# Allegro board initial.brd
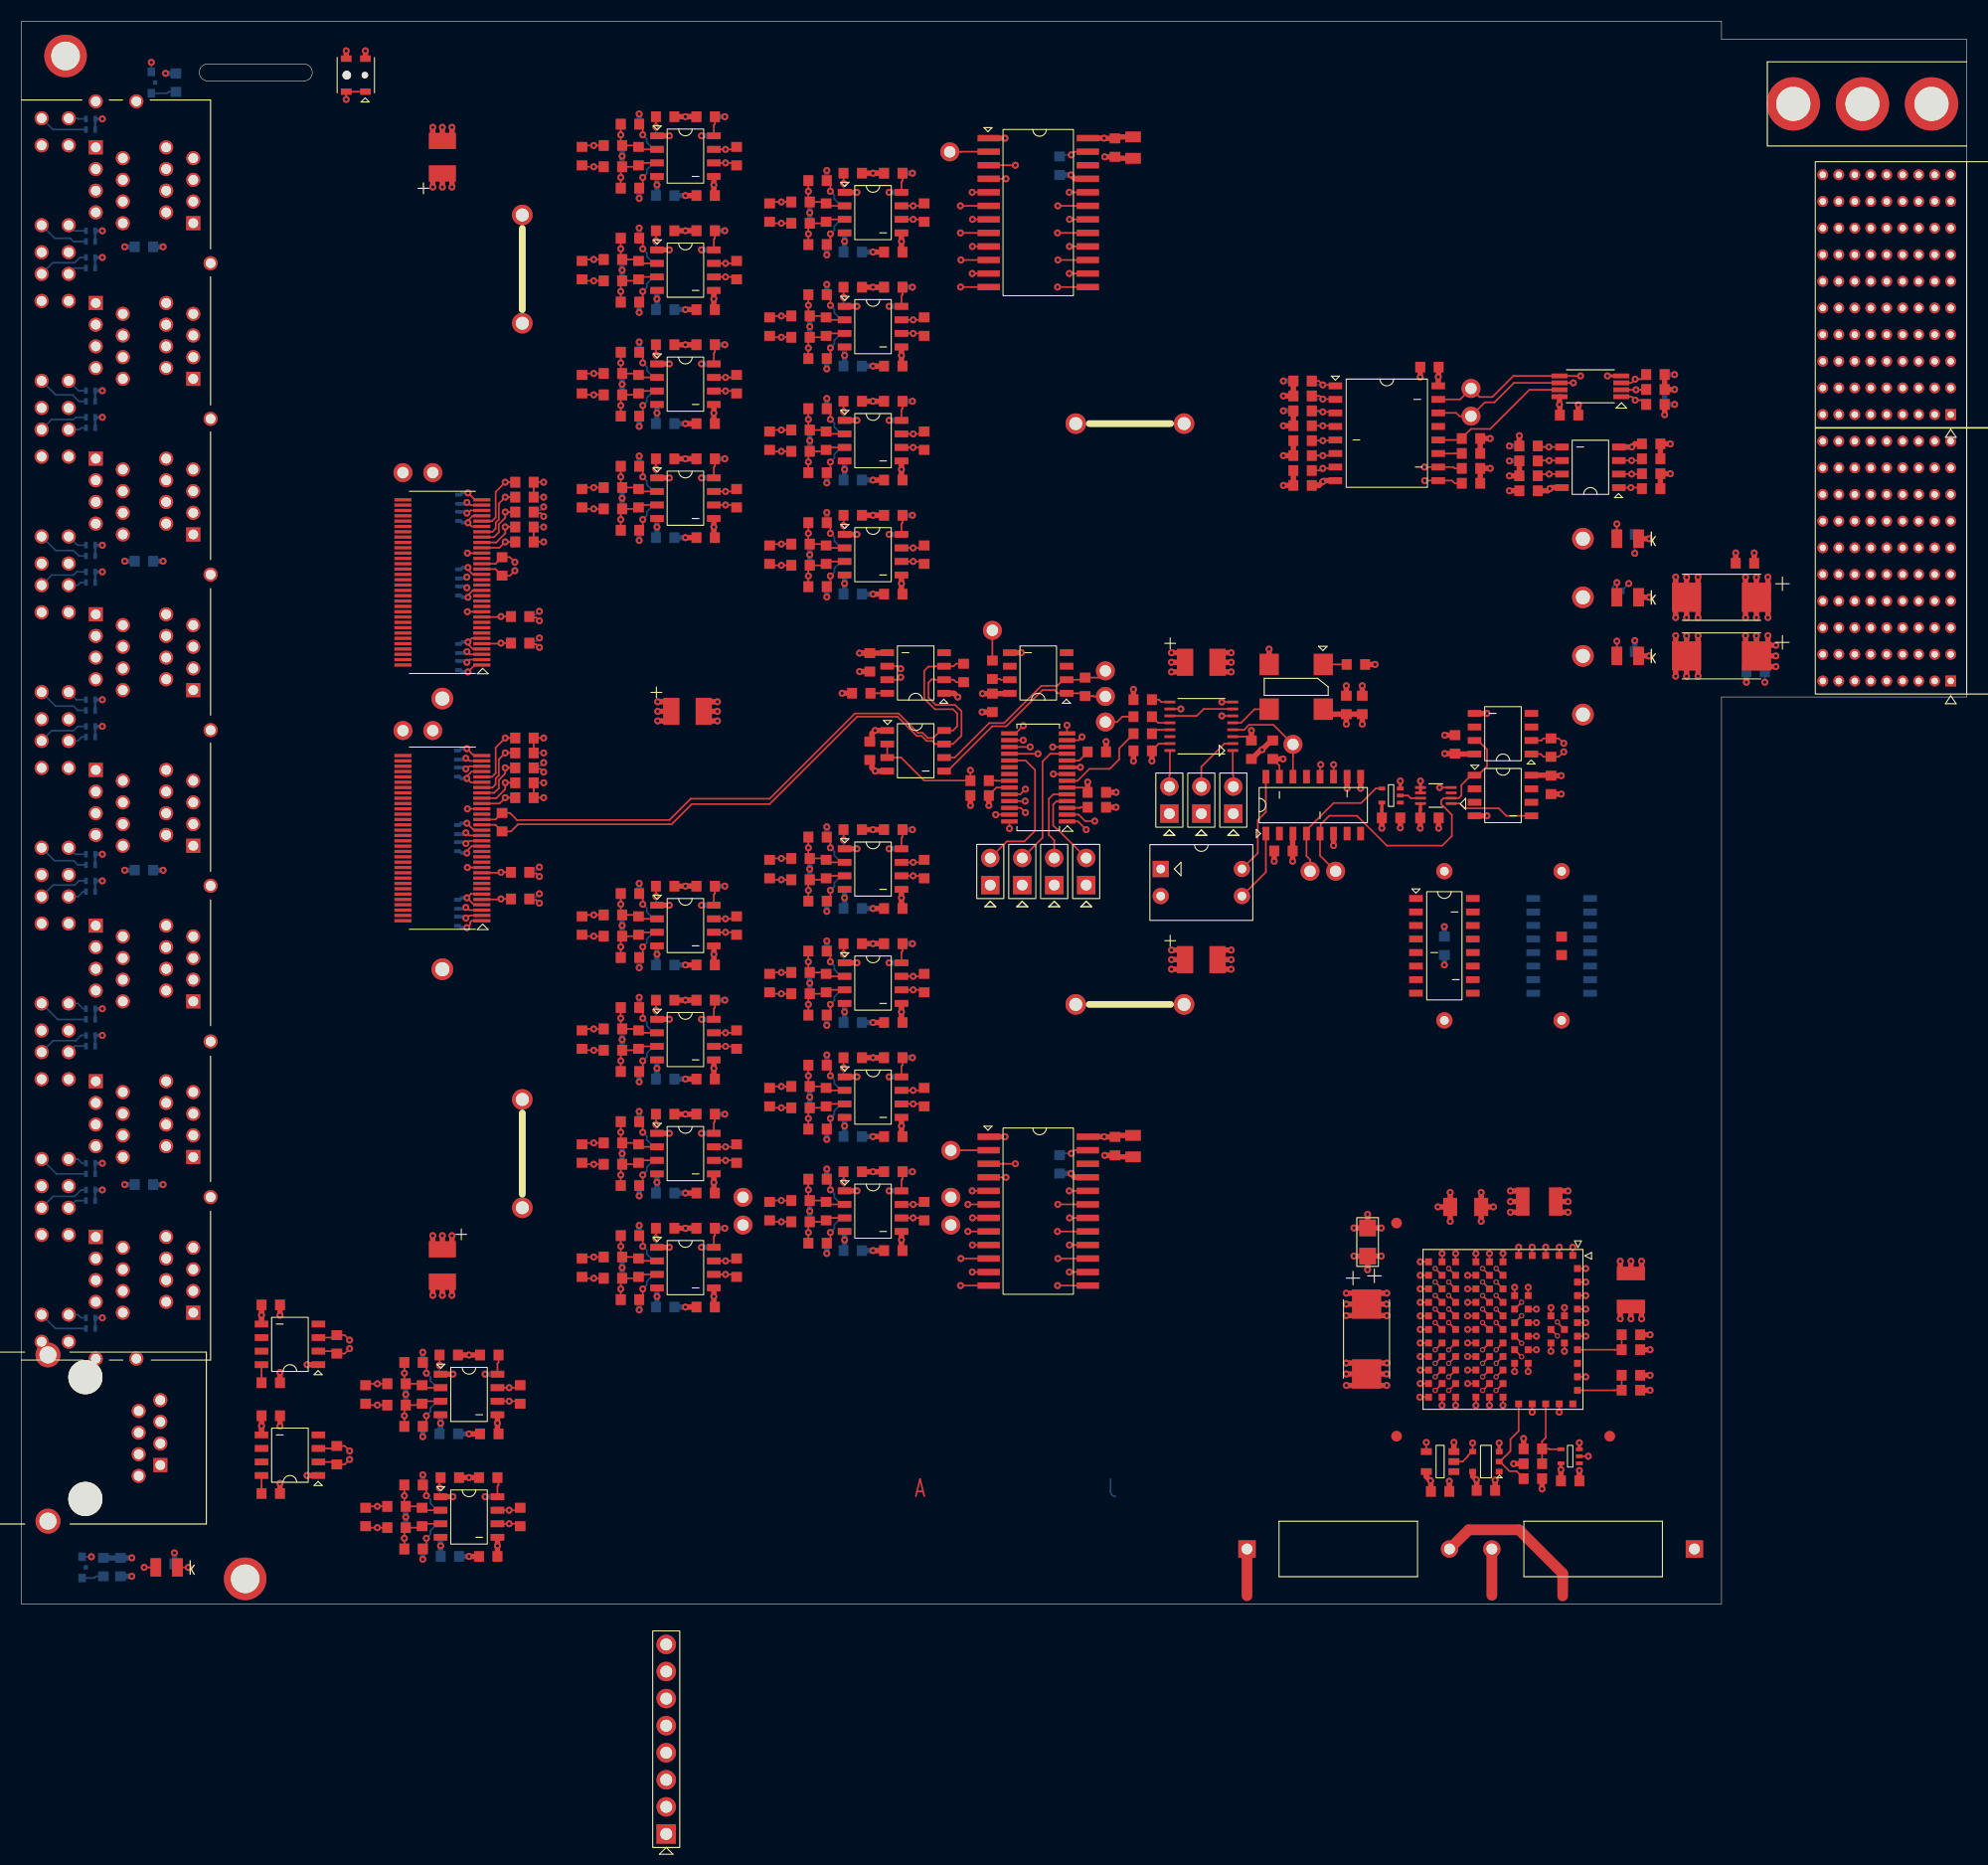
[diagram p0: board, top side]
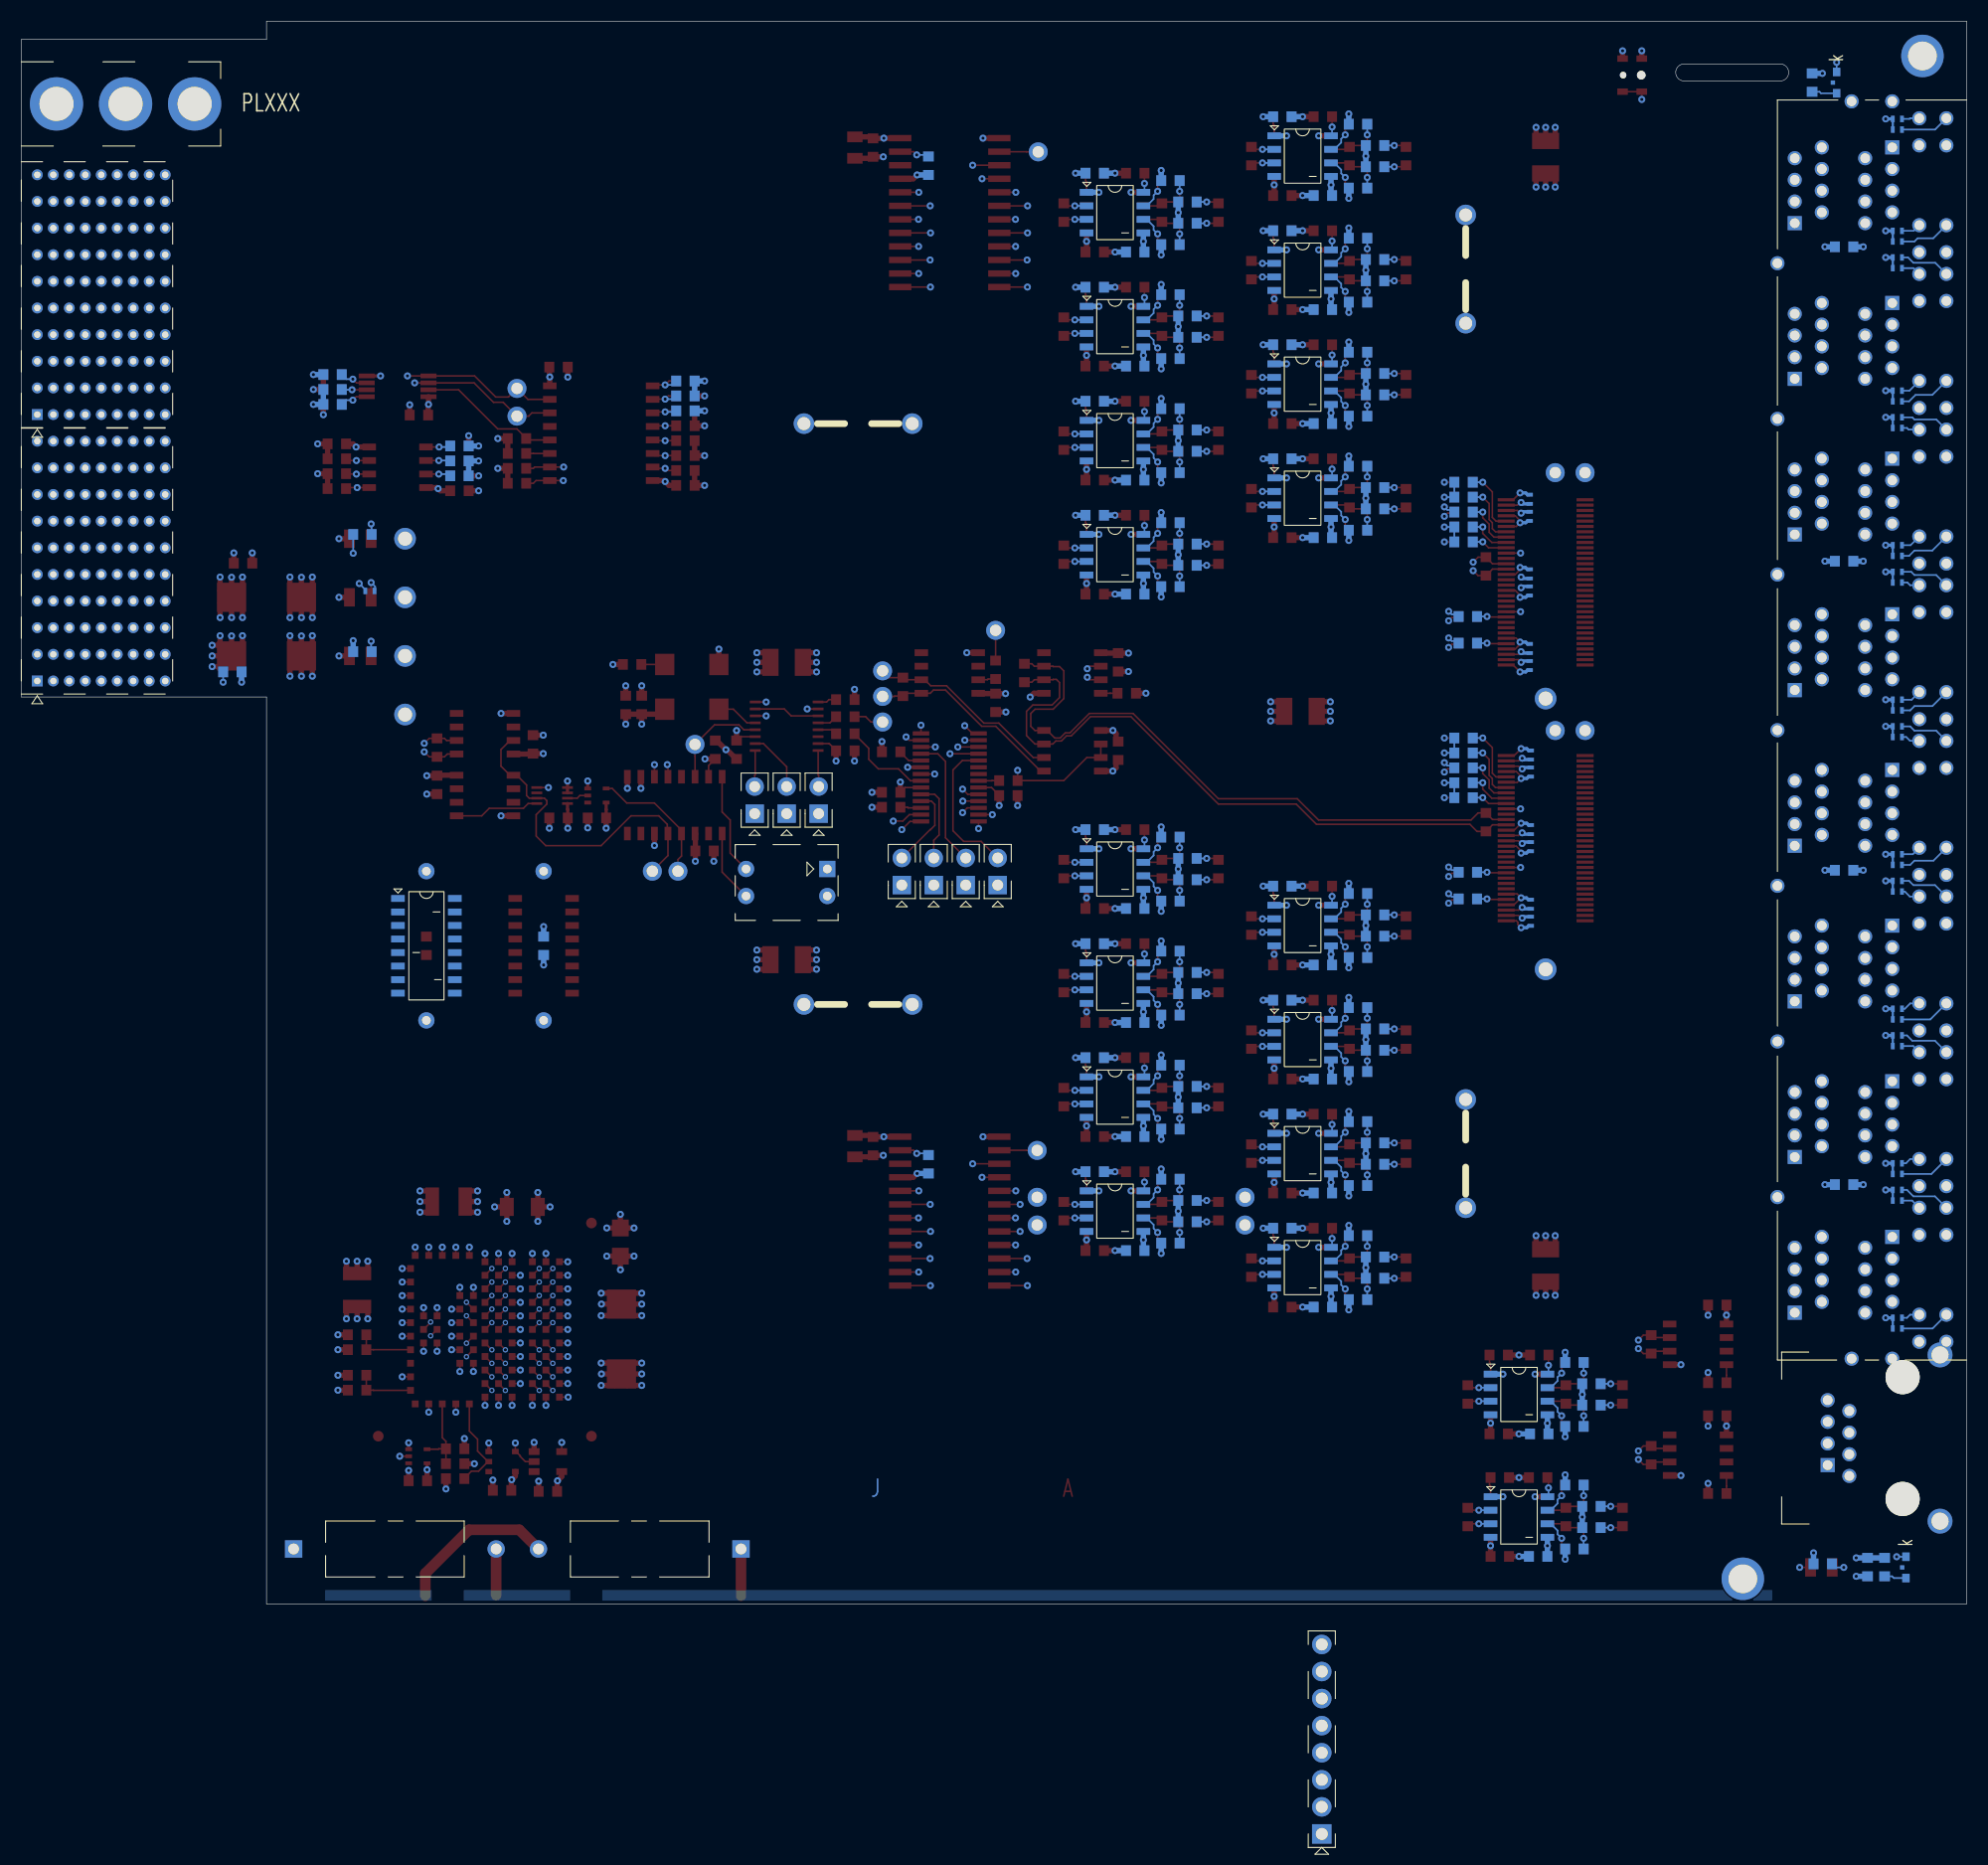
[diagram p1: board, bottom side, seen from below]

Outline 182.5 x 148.5 mm; copper layers: TOP, POWER, INNER TRACKS 1, POWER/GND1, INNER TRACKS 2, INNER TRACKS 3, POWER/GND2, INNER TRACKS 4, GND, BOTTOM. Coordinates in mm from the lower left corner of the outline.
Outline path: 0,148.5 0,0 159.5,0 159.5,85.1 182.5,85.1 182.5,146.8 159.5,146.8 159.5,148.5 0,148.5 ; 17.5,144.5 26.5,144.5 arc(27.3,143.7) 26.5,142.9 17.5,142.9 arc(16.7,143.7) 17.5,144.5

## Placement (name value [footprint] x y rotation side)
C1  -  [SMD0603M]  89.9 75.85 0 top
C2  -  [SMD0603M]  100.9 76.15 180 top
C3  -  [SMD0603M]  134.5 80.65 270 top
C4  -  [SMD0603M]  132.1 73.75 0 top
C5  -  [SMD0603M]  79.6 80.05 90 top
C6  -  [SMD0603M]  91.1 84.55 90 top
C7  -  [SMD0603M]  143.5 76.85 90 top
C8  -  [SMD0603M]  79.6 88.35 90 top
C9  -  [SMD0603M]  128.5 73.75 180 top
C10  -  [SMD0603M]  124.3 84.35 270 top
C11  -  [SMD0603M]  125.8 84.35 270 top
C12  -  [SMD0603M]  118.4 70.65 0 top
C13  -  [SMD0603M]  117.4 80.15 270 top
C14  -  [SMD0402]  40.9 65.65 270 bottom
C15  -  [SMD0402]  40.9 72.65 270 bottom
C16  -  [SMD0402]  40.9 79.65 270 bottom
C17  -  [SMD0402]  40.9 64.05 90 bottom
C18  -  [SMD0603]  55.5 134.85 180 bottom
C19  -  [SMD0603]  55.5 136.85 180 bottom
C20  -  [SMD0402]  40.9 71.05 90 bottom
C21  -  [SMD0402]  40.9 78.05 90 bottom
C22  -  [SMD0603M]  55.5 136.85 0 top
C23  -  [SMD0603M]  55.5 134.85 0 top
C24  -  [SMD0603M]  105.2 80.05 0 top
C25  -  [SMD0603M]  115.4 80.15 90 top
C26  -  [SMD0402]  41 103.65 270 bottom
C27  -  [SMD0402]  41 102.05 90 bottom
C28  -  [SMD0402]  41 96.65 270 bottom
C29  -  [SMD0402]  41 95.05 90 bottom
C30  -  [SMD0402]  41 89.65 270 bottom
C31  -  [SMD0402]  41 88.05 90 bottom
C32  -  [SMD0603]  35.2 7.15 180 bottom
C33  -  [SMD0603]  35.2 18.65 180 bottom
C34  -  [SMD0603]  35.2 9.15 180 bottom
C35  -  [SMD0603]  35.2 20.65 180 bottom
C36  -  [SMD0603M]  35.2 9.15 0 top
C37  -  [SMD0603M]  35.2 7.15 0 top
C38  -  [SMD0603M]  35.2 20.65 0 top
C39  -  [SMD0603M]  35.2 18.65 0 top
C40  -  [SMD0603M]  43.8 4.45 0 top
C41  -  [SMD0603M]  40.2 4.45 180 bottom
C42  -  [SMD0603M]  43.9 15.95 0 top
C43  -  [SMD0603M]  40.1 15.95 180 bottom
C44  -  [SMD0603M]  23.4 28.05 180 top
C45  -  [SMD0603M]  23.4 17.65 180 top
C46  -  [CASE_B]  62.5 83.75 180 top
C47  -  [CASE_B]  39.5 135.75 270 top
C48  -  [CASE_B]  39.5 31.75 90 top
C49  -  [CASE_B]  110.7 60.45 180 top
C50  -  [CASE_B]  110.7 88.35 180 top
C51  -  [SMD0603M]  64.2 118.15 180 bottom
C52  -  [SMD0603M]  64.2 139.55 180 bottom
C53  -  [SMD0603]  55.5 113.45 180 bottom
C54  -  [SMD0603M]  60.4 110.75 180 bottom
C55  -  [SMD0603M]  60.4 132.15 180 bottom
C56  -  [SMD0603]  55.5 115.45 180 bottom
C57  -  [SMD0603M]  64.2 110.75 0 top
C58  -  [SMD0603M]  64.2 132.15 0 top
C59  -  [SMD0603M]  55.5 115.45 0 top
C60  -  [SMD0603M]  55.5 113.45 0 top
C61  -  [SMD0603M]  64.2 107.45 180 bottom
C62  -  [SMD0603M]  64.2 128.85 180 bottom
C63  -  [SMD0603M]  60.4 100.05 180 bottom
C64  -  [SMD0603M]  60.4 121.45 180 bottom
C65  -  [SMD0603]  55.5 102.75 180 bottom
C66  -  [SMD0603]  55.5 124.15 180 bottom
C67  -  [SMD0603M]  64.2 100.05 0 top
C68  -  [SMD0603]  55.5 104.75 180 bottom
C69  -  [SMD0603]  55.5 126.15 180 bottom
C70  -  [SMD0603M]  64.2 121.45 0 top
C71  -  [SMD0603M]  55.5 104.75 0 top
C72  -  [SMD0603M]  55.5 102.75 0 top
C73  -  [SMD0603M]  55.5 126.15 0 top
C74  -  [SMD0603M]  55.5 124.15 0 top
C75  -  [SMD0603M]  133.1 10.55 180 top
C76  -  [SMD0603M]  137.4 10.65 180 top
C77  -  [SMD0603M]  132.1 116.05 0 top
C78  -  [CASE_D]  159.5 88.95 0 top
C79  -  [SMD1210M]  142.4 37.75 0 top
C80  -  [SMD1210M]  151 29.45 90 top
C81  -  [SMD0603]  151 25.25 180 top
C82  -  [SMD0603M]  151 21.45 0 top
C83  -  [SMD1206]  135.5 37.25 180 top
C84  -  [CASE_E]  126.2 24.85 90 top
C85  -  [SMD0603M]  145.2 111.55 180 top
C86  -  [SMD0603M]  9.3 3.45 90 bottom
C87  -  [SMD0603M]  120.2 104.95 180 top
C88  -  [SMD0603M]  152.9 108.85 0 top
C89  -  [SMD0603M]  161.7 97.65 0 top
C90  -  [SMD0603M]  141.4 104.45 0 top
C91  -  [CASE_E]  159.5 94.45 0 top
C92  -  [SMD0603M]  64.2 45.95 180 bottom
C93  -  [SMD0603M]  64.2 67.35 180 bottom
C94  -  [SMD0603]  55.5 41.25 180 bottom
C95  -  [SMD0603M]  60.4 38.55 180 bottom
C96  -  [SMD0603M]  60.4 59.95 180 bottom
C97  -  [SMD0603]  55.5 62.65 180 bottom
C98  -  [SMD0603]  55.5 43.25 180 bottom
C99  -  [SMD0603M]  64.2 38.55 0 top
C100  -  [SMD0603]  55.5 64.65 180 bottom
C101  -  [SMD0603M]  64.2 59.95 0 top
C102  -  [SMD0603M]  55.5 43.25 0 top
C103  -  [SMD0603M]  55.5 41.25 0 top
C104  -  [SMD0603M]  55.5 64.65 0 top
C105  -  [SMD0603M]  55.5 62.65 0 top
C106  -  [SMD0603M]  64.2 35.25 180 bottom
C107  -  [SMD0603M]  64.2 56.65 180 bottom
C108  -  [SMD0603M]  60.4 27.85 180 bottom
C109  -  [SMD0603M]  60.4 49.25 180 bottom
C110  -  [SMD0603]  55.5 30.55 180 bottom
C111  -  [SMD0603]  55.5 51.95 180 bottom
C112  -  [SMD0603]  55.5 32.55 180 bottom
C113  -  [SMD0603]  55.5 53.95 180 bottom
C114  -  [SMD0603M]  64.2 27.85 0 top
C115  -  [SMD0603M]  64.2 49.25 0 top
C116  -  [SMD0603M]  55.5 32.55 0 top
C117  -  [SMD0603M]  55.5 30.55 0 top
C118  -  [SMD0603M]  55.5 53.95 0 top
C119  -  [SMD0603M]  55.5 51.95 0 top
C120  -  [SMD0603M]  81.8 72.65 180 bottom
C121  -  [SMD0603M]  81.8 43.85 0 top
C122  -  [SMD0603]  73.1 46.55 180 bottom
C123  -  [SMD0603M]  78 65.25 180 bottom
C124  -  [SMD0603M]  78 43.85 180 bottom
C125  -  [SMD0603]  73.1 67.95 180 bottom
C126  -  [SMD0603]  73.1 48.55 180 bottom
C127  -  [SMD0603]  73.1 69.95 180 bottom
C128  -  [SMD0603M]  81.8 65.25 0 top
C129  -  [SMD0603M]  81.8 51.25 180 bottom
C130  -  [SMD0603M]  73.1 48.55 0 top
C131  -  [SMD0603M]  73.1 46.55 0 top
C132  -  [SMD0603M]  73.1 69.95 0 top
C133  -  [SMD0603M]  73.1 67.95 0 top
C134  -  [SMD0603M]  81.8 54.55 0 top
C135  -  [SMD0603M]  81.8 40.55 180 bottom
C136  -  [SMD0603M]  78 54.55 180 bottom
C137  -  [SMD0603]  73.1 35.85 180 bottom
C138  -  [SMD0603M]  81.8 33.15 0 top
C139  -  [SMD0603]  73.1 57.25 180 bottom
C140  -  [SMD0603]  73.1 37.85 180 bottom
C141  -  [SMD0603]  73.1 59.25 180 bottom
C142  -  [SMD0603M]  81.8 61.95 180 bottom
C143  -  [SMD0603M]  78 33.15 180 bottom
C144  -  [SMD0603M]  73.1 37.85 0 top
C145  -  [SMD0603M]  73.1 35.85 0 top
C146  -  [SMD0603M]  73.1 59.25 0 top
C147  -  [SMD0603M]  73.1 57.25 0 top
C148  -  [SMD0603M]  81.8 134.25 180 bottom
C149  -  [SMD0603M]  81.8 112.85 180 bottom
C150  -  [SMD0603]  73.1 108.15 180 bottom
C151  -  [SMD0603M]  78 126.85 180 bottom
C152  -  [SMD0603M]  78 105.45 180 bottom
C153  -  [SMD0603]  73.1 129.55 180 bottom
C154  -  [SMD0603]  73.1 110.15 180 bottom
C155  -  [SMD0603]  73.1 131.55 180 bottom
C156  -  [SMD0603M]  81.8 126.85 0 top
C157  -  [SMD0603M]  81.8 105.45 0 top
C158  -  [SMD0603M]  73.1 110.15 0 top
C159  -  [SMD0603M]  73.1 108.15 0 top
C160  -  [SMD0603M]  73.1 131.55 0 top
C161  -  [SMD0603M]  73.1 129.55 0 top
C162  -  [SMD0603M]  81.8 123.55 180 bottom
C163  -  [SMD0603M]  81.8 102.15 180 bottom
C164  -  [SMD0603M]  78 116.15 180 bottom
C165  -  [SMD0603]  73.1 97.45 180 bottom
C166  -  [SMD0603M]  78 94.75 180 bottom
C167  -  [SMD0603]  73.1 118.85 180 bottom
C168  -  [SMD0603]  73.1 99.45 180 bottom
C169  -  [SMD0603]  73.1 120.85 180 bottom
C170  -  [SMD0603M]  81.8 116.15 0 top
C171  -  [SMD0603M]  81.8 94.75 0 top
C172  -  [SMD0603M]  73.1 99.45 0 top
C173  -  [SMD0603M]  73.1 97.45 0 top
C174  -  [SMD0603M]  73.1 120.85 0 top
C175  -  [SMD0603M]  73.1 118.85 0 top
C176  -  [SMD0603M]  11.5 127.34 180 bottom
C177  -  [SMD0603M]  11.5 97.84 180 bottom
C178  -  [SMD0603M]  11.5 68.84 180 bottom
C179  -  [SMD0603M]  11.5 39.34 180 bottom
C180  -  [SMD0603M]  145.3 11.55 180 top
C181  -  [SMD0603M]  102.6 136.65 90 top
C182  -  [SMD0805M]  104.3 136.65 90 top
C183  -  [SMD0603M]  102.6 42.95 90 top
C184  -  [SMD0805M]  104.3 42.95 90 top
C185  -  [CASE_A]  126.3 33.95 270 top
C186  -  [SMD0603M]  133.5 61.75 90 bottom
C187  -  [SMD0603M]  144.5 61.75 90 top
DS1  -  [SMD0805_LED]  13.63 3.42 0 top
DS2  -  [SMD0805_LED]  150.7 88.95 0 top
DS3  -  [SMD0805_LED]  150.7 94.45 0 top
DS4  -  [SMD0805_LED]  150.7 99.95 0 top
DS5  -  [LED_C120]  12.2 142.75 90 bottom
DS6  -  [LED_C120]  5.7 3.42 90 bottom
LK5  -  [JUMPER2X1_0-4]  47 130.33 270 top
LK6  -  [JUMPER2X1_0-4]  47 47.33 270 top
LK7  -  [JUMPER2X1_0-4]  98.92 110.75 0 top
LK8  -  [JUMPER2X1_0-4]  98.92 56.25 0 top
LK9  -  [1-HOLE_0-8P]  133.5 54.75 0 top
LK10  -  [1-HOLE_0-8P]  144.5 54.75 0 top
LK11  -  [1-HOLE_0-8P]  133.5 68.75 0 top
LK12  -  [1-HOLE_0-8P]  144.5 68.75 0 top
NOREF  -  []  324.06 192.95 0 top
NOREF#2  -  []  338.25 207.28 270 top
NOREF#3  -  []  303.96 193.41 0 top
NOREF#4  -  []  301.8 201.69 0 top
NOREF#5  -  []  305.51 178.63 0 top
NOREF#6  -  [unnamed#3]  4.15 145.25 0 top
NOREF#7  -  []  126.54 -124.33 0 top
NOREF#8  -  []  14.14 -124.33 0 top
NOREF#9  -  [unnamed#3]  21 2.35 0 top
NOREF#10  -  []  314.1 193.26 0 top
NOREF#11  -  []  317.37 209.01 180 top
NOREF#12  -  []  -79.18 -149.14 0 top
NOREF#13  -  []  302.03 169.94 0 top
NOREF#14  -  []  330.15 201.21 90 top
PL1  -  [HEADER2X1_STR]  93.9 67.45 90 top
PL2  -  [HEADER2X1_STR]  99.9 67.45 90 top
PL3  -  [HEADER2X1_STR]  96.9 67.45 90 top
PL4  -  [HEADER2X1_STR]  90.9 67.45 90 top
PL5  -  [HEADER2X1_STR]  107.7 74.15 90 top
PL6  -  [HEADER2X1_STR]  113.7 74.15 90 top
PL7  -  [HEADER2X1_STR]  110.7 74.15 90 top
PL8  -  [UNIVERSAL_GUIDE_PIN]  179.2 140.75 180 top
PL9  -  [PL_DIFF_30PAIRS_RT-ANG]  181 86.6 90 top
PL10  -  [PL_DIFF_30PAIRS_RT-ANG]  181 111.6 90 top
PL11  -  [HEADER1X8_STR]  60.5 -31.75 90 top
R1  -  [SMD0603]  100.9 74.75 180 top
R2  -  [SMD0603]  100.9 79.95 180 top
R3  -  [SMD0603]  89.9 77.25 180 top
R4  -  [SMD0603]  99.8 86.05 90 top
R5  -  [SMD0603]  91.1 87.65 90 top
R6  -  [SMD0603]  47.2 81.25 0 top
R7  -  [SMD0603]  47.2 81.25 180 bottom
R8  -  [SMD0603]  47.2 75.65 0 top
R9  -  [SMD0603]  47.2 75.65 180 bottom
R10  -  [SMD0603]  46.8 68.65 0 top
R11  -  [SMD0603]  46.8 68.65 180 bottom
R12  -  [SMD0603]  46.8 66.15 0 top
R13  -  [SMD0603]  46.8 66.15 180 bottom
R14  -  [SMD0603]  47.2 79.85 0 top
R15  -  [SMD0603]  47.2 79.85 180 bottom
R16  -  [SMD0603]  47.2 78.45 0 top
R17  -  [SMD0603]  47.2 78.45 180 bottom
R18  -  [SMD0603]  47.2 77.05 0 top
R19  -  [SMD0603]  47.2 77.05 180 bottom
R20  -  [SMD0603]  52.6 135.85 90 top
R21  -  [SMD0603]  88.4 87.35 270 top
R22  -  [SMD0603]  125.2 88.15 0 top
R23  -  [SMD0603]  78.8 85.45 180 top
R24  -  [SMD0603]  57.1 138.85 0 top
R25  -  [SMD0603]  57.9 135.85 90 top
R26  -  [SMD0603]  57.1 132.85 180 top
R27  -  [SMD0603]  57.1 138.85 0 bottom
R28  -  [SMD0603]  57.1 132.85 180 bottom
R29  -  [SMD0603]  105.2 84.85 180 top
R30  -  [SMD0603]  105.2 81.65 180 top
R31  -  [SMD0603]  105.2 83.25 180 top
R32  -  [SMD0402]  6.5 138.34 180 bottom
R33  -  [SMD0402]  6.5 127.84 180 bottom
R34  -  [SMD0402]  6.5 126.34 180 bottom
R35  -  [SMD0603]  64.2 139.55 180 top
R36  -  [SMD0402]  6.5 112.84 180 bottom
R37  -  [SMD0603]  67.1 135.85 90 top
R38  -  [SMD0402]  6.5 111.34 180 bottom
R39  -  [SMD0603]  60.4 139.55 0 top
R40  -  [SMD0402]  6.5 98.34 180 bottom
R41  -  [SMD0402]  6.5 96.84 180 bottom
R42  -  [SMD0402]  6.5 83.84 180 bottom
R43  -  [SMD0402]  6.5 82.34 180 bottom
R44  -  [SMD0402]  6.5 69.34 180 bottom
R45  -  [SMD0402]  6.5 67.84 180 bottom
R46  -  [SMD0402]  6.5 54.84 180 bottom
R47  -  [SMD0402]  6.5 53.34 180 bottom
R48  -  [SMD0402]  6.5 40.34 180 bottom
R49  -  [SMD0402]  6.5 38.84 180 bottom
R50  -  [SMD0402]  6.5 25.84 180 bottom
R51  -  [SMD0402]  6.5 139.34 0 bottom
R52  -  [SMD0402]  6.5 128.84 0 bottom
R53  -  [SMD0402]  6.5 125.34 0 bottom
R54  -  [SMD0402]  6.5 113.84 0 bottom
R55  -  [SMD0402]  6.5 110.34 0 bottom
R56  -  [SMD0402]  6.5 99.34 0 bottom
R57  -  [SMD0402]  6.5 95.84 0 bottom
R58  -  [SMD0402]  6.5 84.84 0 bottom
R59  -  [SMD0402]  6.5 81.34 0 bottom
R60  -  [SMD0402]  6.5 70.34 0 bottom
R61  -  [SMD0402]  6.5 66.84 0 bottom
R62  -  [SMD0402]  6.5 55.84 0 bottom
R63  -  [SMD0402]  6.5 52.34 0 bottom
R64  -  [SMD0402]  6.5 41.34 0 bottom
R65  -  [SMD0402]  6.5 37.84 0 bottom
R66  -  [SMD0402]  6.5 26.84 0 bottom
R67  -  [SMD0603]  45.1 97.35 270 top
R68  -  [SMD0603]  46.8 92.65 0 top
R69  -  [SMD0603]  46.8 92.65 180 bottom
R70  -  [SMD0603]  46.8 90.15 0 top
R71  -  [SMD0603]  46.8 90.15 180 bottom
R72  -  [SMD0603]  47.2 103.85 0 top
R73  -  [SMD0603]  47.2 103.85 180 bottom
R74  -  [SMD0603]  47.2 102.45 0 top
R75  -  [SMD0603]  47.2 102.45 180 bottom
R76  -  [SMD0603]  47.2 101.05 0 top
R77  -  [SMD0603]  47.2 101.05 180 bottom
R78  -  [SMD0603]  47.2 105.25 0 top
R79  -  [SMD0603]  47.2 105.25 180 bottom
R80  -  [SMD0603]  47.2 99.65 0 top
R81  -  [SMD0603]  47.2 99.65 180 bottom
R82  -  [SMD0603]  32.3 8.15 90 top
R83  -  [SMD0603]  32.3 19.65 90 top
R84  -  [SMD0603]  36.8 11.15 0 top
R85  -  [SMD0603]  37.6 8.15 90 top
R86  -  [SMD0603]  36.8 5.15 180 top
R87  -  [SMD0603]  36.8 22.65 0 top
R88  -  [SMD0603]  37.6 19.65 90 top
R89  -  [SMD0603]  36.8 16.65 180 top
R90  -  [SMD0603]  36.8 5.15 180 bottom
R91  -  [SMD0603]  36.8 16.65 180 bottom
R92  -  [SMD0603]  36.8 11.15 0 bottom
R93  -  [SMD0603]  36.8 22.65 0 bottom
R94  -  [SMD0603]  43.8 11.85 180 top
R95  -  [SMD0603]  43.9 23.35 180 top
R96  -  [SMD0603]  46.8 8.15 90 top
R97  -  [SMD0603]  46.8 19.65 90 top
R98  -  [SMD0603]  40.2 11.85 0 top
R99  -  [SMD0603]  40.1 23.35 0 top
R100  -  [SMD0603]  29.6 24.35 270 top
R101  -  [SMD0603]  29.6 13.95 270 top
R102  -  [SMD0603]  23.4 20.75 0 top
R103  -  [SMD0603]  23.4 10.35 0 top
R104  -  [SMD0603]  52.6 114.45 90 top
R105  -  [SMD0603]  57.1 117.45 0 top
R106  -  [SMD0603]  57.9 114.45 90 top
R107  -  [SMD0603]  57.1 111.45 180 top
R108  -  [SMD0603]  57.1 117.45 0 bottom
R109  -  [SMD0603]  57.1 111.45 180 bottom
R110  -  [SMD0603]  64.2 118.15 180 top
R111  -  [SMD0603]  67.1 114.45 90 top
R112  -  [SMD0603]  60.4 118.15 0 top
R113  -  [SMD0603]  52.6 103.75 90 top
R114  -  [SMD0603]  52.6 125.15 90 top
R115  -  [SMD0603]  57.1 106.75 0 top
R116  -  [SMD0603]  57.9 103.75 90 top
R117  -  [SMD0603]  57.1 100.75 180 top
R118  -  [SMD0603]  57.1 128.15 0 top
R119  -  [SMD0603]  57.9 125.15 90 top
R120  -  [SMD0603]  57.1 122.15 180 top
R121  -  [SMD0603]  57.1 106.75 0 bottom
R122  -  [SMD0603]  57.1 100.75 180 bottom
R123  -  [SMD0603]  57.1 128.15 0 bottom
R124  -  [SMD0603]  57.1 122.15 180 bottom
R125  -  [SMD0603]  64.2 107.45 180 top
R126  -  [SMD0603]  64.2 128.85 180 top
R127  -  [SMD0603]  67.1 103.75 90 top
R128  -  [SMD0603]  67.1 125.15 90 top
R129  -  [SMD0603]  60.4 107.45 0 top
R130  -  [SMD0603]  60.4 128.85 0 top
R131  -  [SMD0603]  150.5 89.35 180 bottom
R132  -  [SMD0402]  149.8 95.05 180 bottom
R133  -  [SMD0603]  141.8 11.75 0 top
R134  -  [SMD0603]  150.5 100.35 180 bottom
R135  -  [SMD0603]  141.8 14.55 180 top
R136  -  [SMD0603]  141.8 13.15 0 top
R137  -  [SMD0603]  151 23.85 180 top
R138  -  [SMD0603]  120.2 114.75 180 top
R139  -  [SMD0603]  120.2 110.55 180 top
R140  -  [SMD0603]  120.2 109.15 180 top
R141  -  [SMD0603]  120.2 107.75 180 top
R142  -  [SMD0603]  120.2 106.35 180 top
R143  -  [SMD0603]  136 105.15 0 top
R144  -  [SMD0603]  151 20.05 180 top
R145  -  [SMD0603]  136 106.55 0 top
R146  -  [SMD0603]  136 107.95 0 top
R147  -  [SMD0603]  136 109.35 0 top
R148  -  [SMD0603]  153.3 115.35 0 top
R149  -  [SMD0603]  152.9 104.65 0 top
R150  -  [SMD0603]  152.9 106.05 0 top
R151  -  [SMD0603]  14.5 142.75 270 bottom
R152  -  [SMD0603]  7.7 3.45 270 bottom
R153  -  [SMD0603]  13.5 3.75 180 bottom
R154  -  [SMD0603]  141.4 108.65 180 top
R155  -  [SMD0603]  141.4 108.65 0 bottom
R156  -  [SMD0603]  141.4 107.25 180 top
R157  -  [SMD0603]  141.4 107.25 0 bottom
R158  -  [SMD0603]  141.4 105.85 180 top
R159  -  [SMD0603]  141.4 105.85 0 bottom
R160  -  [SMD0603]  152.9 107.45 0 top
R161  -  [SMD0603]  52.6 42.25 90 top
R162  -  [SMD0603]  52.6 63.65 90 top
R163  -  [SMD0603]  57.1 45.25 0 top
R164  -  [SMD0603]  57.9 42.25 90 top
R165  -  [SMD0603]  57.1 39.25 180 top
R166  -  [SMD0603]  57.1 45.25 0 bottom
R167  -  [SMD0603]  57.1 39.25 180 bottom
R168  -  [SMD0603]  57.1 66.65 0 top
R169  -  [SMD0603]  57.9 63.65 90 top
R170  -  [SMD0603]  57.1 60.65 180 top
R171  -  [SMD0603]  57.1 66.65 0 bottom
R172  -  [SMD0603]  57.1 60.65 180 bottom
R173  -  [SMD0603]  64.2 45.95 180 top
R174  -  [SMD0603]  64.2 67.35 180 top
R175  -  [SMD0603]  67.1 42.25 90 top
R176  -  [SMD0603]  67.1 63.65 90 top
R177  -  [SMD0603]  60.4 45.95 0 top
R178  -  [SMD0603]  60.4 67.35 0 top
R179  -  [SMD0603]  52.6 31.55 90 top
R180  -  [SMD0603]  52.6 52.95 90 top
R181  -  [SMD0603]  57.1 34.55 0 top
R182  -  [SMD0603]  57.9 31.55 90 top
R183  -  [SMD0603]  57.1 28.55 180 top
R184  -  [SMD0603]  57.1 55.95 0 top
R185  -  [SMD0603]  57.9 52.95 90 top
R186  -  [SMD0603]  57.1 49.95 180 top
R187  -  [SMD0603]  57.1 34.55 0 bottom
R188  -  [SMD0603]  57.1 28.55 180 bottom
R189  -  [SMD0603]  57.1 55.95 0 bottom
R190  -  [SMD0603]  57.1 49.95 180 bottom
R191  -  [SMD0603]  64.2 35.25 180 top
R192  -  [SMD0603]  64.2 56.65 180 top
R193  -  [SMD0603]  67.1 31.55 90 top
R194  -  [SMD0603]  67.1 52.95 90 top
R195  -  [SMD0603]  60.4 35.25 0 top
R196  -  [SMD0603]  60.4 56.65 0 top
R197  -  [SMD0603]  70.2 47.55 90 top
R198  -  [SMD0603]  70.2 68.95 90 top
R199  -  [SMD0603]  74.7 50.55 0 top
R200  -  [SMD0603]  75.5 47.55 90 top
R201  -  [SMD0603]  74.7 44.55 180 top
R202  -  [SMD0603]  74.7 50.55 0 bottom
R203  -  [SMD0603]  74.7 44.55 180 bottom
R204  -  [SMD0603]  74.7 71.95 0 top
R205  -  [SMD0603]  75.5 68.95 90 top
R206  -  [SMD0603]  74.7 65.95 180 top
R207  -  [SMD0603]  74.7 71.95 0 bottom
R208  -  [SMD0603]  74.7 65.95 180 bottom
R209  -  [SMD0603]  81.8 51.25 180 top
R210  -  [SMD0603]  81.8 72.65 180 top
R211  -  [SMD0603]  84.7 47.55 90 top
R212  -  [SMD0603]  84.7 68.95 90 top
R213  -  [SMD0603]  78 51.25 0 top
R214  -  [SMD0603]  78 72.65 0 top
R215  -  [SMD0603]  70.2 36.85 90 top
R216  -  [SMD0603]  70.2 58.25 90 top
R217  -  [SMD0603]  74.7 39.85 0 top
R218  -  [SMD0603]  75.5 36.85 90 top
R219  -  [SMD0603]  74.7 33.85 180 top
R220  -  [SMD0603]  74.7 61.25 0 top
R221  -  [SMD0603]  75.5 58.25 90 top
R222  -  [SMD0603]  74.7 55.25 180 top
R223  -  [SMD0603]  74.7 39.85 0 bottom
R224  -  [SMD0603]  74.7 33.85 180 bottom
R225  -  [SMD0603]  74.7 61.25 0 bottom
R226  -  [SMD0603]  74.7 55.25 180 bottom
R227  -  [SMD0603]  81.8 40.55 180 top
R228  -  [SMD0603]  81.8 61.95 180 top
R229  -  [SMD0603]  84.7 36.85 90 top
R230  -  [SMD0603]  84.7 58.25 90 top
R231  -  [SMD0603]  78 40.55 0 top
R232  -  [SMD0603]  78 61.95 0 top
R233  -  [SMD0603]  70.2 109.15 90 top
R234  -  [SMD0603]  70.2 130.55 90 top
R235  -  [SMD0603]  74.7 112.15 0 top
R236  -  [SMD0603]  75.5 109.15 90 top
R237  -  [SMD0603]  74.7 106.15 180 top
R238  -  [SMD0603]  74.7 112.15 0 bottom
R239  -  [SMD0603]  74.7 106.15 180 bottom
R240  -  [SMD0603]  74.7 133.55 0 top
R241  -  [SMD0603]  75.5 130.55 90 top
R242  -  [SMD0603]  74.7 127.55 180 top
R243  -  [SMD0603]  74.7 133.55 0 bottom
R244  -  [SMD0603]  74.7 127.55 180 bottom
R245  -  [SMD0603]  81.8 112.85 180 top
R246  -  [SMD0603]  81.8 134.25 180 top
R247  -  [SMD0603]  84.7 109.15 90 top
R248  -  [SMD0603]  84.7 130.55 90 top
R249  -  [SMD0603]  78 112.85 0 top
R250  -  [SMD0603]  78 134.25 0 top
R251  -  [SMD0603]  70.2 98.45 90 top
R252  -  [SMD0603]  70.2 119.85 90 top
R253  -  [SMD0603]  74.7 101.45 0 top
R254  -  [SMD0603]  75.5 98.45 90 top
R255  -  [SMD0603]  74.7 95.45 180 top
R256  -  [SMD0603]  74.7 122.85 0 top
R257  -  [SMD0603]  75.5 119.85 90 top
R258  -  [SMD0603]  74.7 116.85 180 top
R259  -  [SMD0603]  74.7 101.45 0 bottom
R260  -  [SMD0603]  74.7 95.45 180 bottom
R261  -  [SMD0603]  74.7 122.85 0 bottom
R262  -  [SMD0603]  74.7 116.85 180 bottom
R263  -  [SMD0603]  81.8 102.15 180 top
R264  -  [SMD0603]  81.8 123.55 180 top
R265  -  [SMD0603]  84.7 98.45 90 top
R266  -  [SMD0603]  84.7 119.85 90 top
R267  -  [SMD0603]  78 102.15 0 top
R268  -  [SMD0603]  78 123.55 0 top
R269  -  [SMD0603]  45.1 73.35 270 top
R270  -  [SMD0603]  162.7 87.45 0 bottom
R271  -  [SMD0603]  97.4 134.95 90 bottom
R272  -  [SMD0603]  97.4 41.25 90 bottom
R273  -  [SMD0603]  143.5 80.35 90 top
R274  -  [MGRF1W]  124.48 5.15 0 top
R275  -  [MGRF1W]  147.45 5.15 180 top
R309  -  [SMD0603]  120.2 111.95 180 top
R310  -  [SMD0603]  120.2 111.95 0 bottom
R311  -  [SMD0603]  120.2 113.35 180 top
R312  -  [SMD0603]  120.2 113.35 0 bottom
R313  -  [SMD0603]  120.2 114.75 0 bottom
R314  -  [SMD0603]  153.3 112.55 0 top
R315  -  [SMD0603]  153.3 112.55 180 bottom
R316  -  [SMD0603]  153.3 113.95 0 top
R317  -  [SMD0603]  153.3 113.95 180 bottom
R318  -  [SMD0603]  153.3 115.35 180 bottom
SK2  -  [RJ45_CAT6_WS_VER1]  12.36 15.56 270 top
SK4  -  [RJ45_2X8PORT_RT]  6.99 136.67 270 top
SW1  -  [SW4-3]  110.7 65.15 0 top
SW2  -  [AMC_MICROSWITCH_SMD_STR]  31.38 143.45 180 top
TP1  -  [1-HOLE_1-05P]  67.7 38.15 0 top
TP2  -  [1-HOLE_1-05P]  67.7 35.55 0 top
TP3  -  [1-HOLE_1-05P]  87.2 35.55 0 top
TP4  -  [1-HOLE_1-05P]  87.2 38.15 0 top
TP5  -  [VERO_TP_1_32MM]  146.5 83.45 0 top
TP6  -  [VERO_TP_1_32MM]  146.5 99.95 0 top
TP7  -  [1-HOLE_1-05P]  136 114.05 0 top
TP8  -  [1-HOLE_1-05P]  136 111.45 0 top
TP9  -  [VERO_TP_1_32MM]  146.5 94.45 0 top
TP10  -  [1-HOLE_1-05P]  101.7 85.15 0 top
TP11  -  [1-HOLE_1-05P]  101.7 87.55 0 top
TP12  -  [1-HOLE_1-05P]  91.1 91.35 0 top
TP13  -  [1-HOLE_1-05P]  123.3 68.75 0 top
TP14  -  [1-HOLE_1-05P]  120.9 68.75 0 top
TP15  -  [1-HOLE_1-05P]  38.6 81.95 0 top
TP16  -  [1-HOLE_1-05P]  35.8 81.95 0 top
TP17  -  [1-HOLE_1-05P]  119.3 80.65 0 top
TP18  -  [1-HOLE_1-05P]  101.7 82.75 0 top
TP19  -  [VERO_TP_1_32MM]  39.5 84.95 0 top
TP20  -  [1-HOLE_1-05P]  87.1 136.25 0 top
TP21  -  [1-HOLE_1-05P]  38.6 106.15 0 top
TP22  -  [1-HOLE_1-05P]  35.8 106.15 0 top
TP23  -  [1-HOLE_1-05P]  87.2 42.55 0 top
TP24  -  [VERO_TP_1_32MM]  39.5 59.55 0 top
TP25  -  [VERO_TP_1_32MM]  146.5 88.95 0 top
U1  -  [SOT23-5_VER2]  133.1 13.35 180 top
U2  -  [SOIC8]  79.9 130.55 0 top
U3  -  [SSOP28_IDT_VER2]  95.4 77.55 180 top
U4  -  [SOIC8]  139 81.65 180 top
U5  -  [VSSOP8]  132.7 75.85 180 top
U6  -  [SOIC8]  95.4 87.35 180 top
U7  -  [SOIC8]  62.3 135.85 0 top
U8  -  [SOIC8]  139 75.85 0 top
U9  -  [SOIC8]  62.3 135.85 180 bottom
U10  -  [SOIC8]  83.9 80.05 0 top
U11  -  [SOT23-5_VER4]  128.5 75.85 180 top
U12  -  [TSSOP64_VER2]  39.5 71.85 180 top
U13  -  [SOIC8]  83.9 87.35 180 top
U14  -  [SOIC16]  121.2 74.95 90 top
U15  -  [CFPS-73]  119.6 86.05 180 top
U16  -  [TSSOP16]  110.7 82.35 180 top
U17  -  [TSSOP64_VER2]  39.5 95.85 180 top
U18  -  [SOIC8]  42 8.15 0 top
U19  -  [SOIC8]  42 19.65 0 top
U20  -  [SOIC8]  42 8.15 180 bottom
U21  -  [SOIC8]  42 19.65 180 bottom
U22  -  [SOIC8]  25.2 24.35 180 top
U23  -  [SOIC8]  25.2 13.95 180 top
U24  -  [SOIC8]  62.3 114.45 0 top
U25  -  [SOIC8]  62.3 114.45 180 bottom
U26  -  [SOIC8]  62.3 103.75 0 top
U27  -  [SOIC8]  62.3 125.15 0 top
U28  -  [SOIC8]  62.3 103.75 180 bottom
U29  -  [SOIC8]  62.3 125.15 180 bottom
U30  -  [SOT23-5]  137.4 13.35 180 top
U31  -  [SOT23-5_VER4]  145.3 13.85 180 top
U32  -  [SOIC16-3]  128.1 109.85 0 top
U33  -  [LGA104]  139 25.75 270 top
U34  -  [TSSOP8_VER6]  147.2 114.25 180 top
U35  -  [SOIC8]  147.2 106.65 180 top
U36  -  [SOIC8]  62.3 42.25 0 top
U37  -  [SOIC8]  62.3 63.65 0 top
U38  -  [SOIC8]  62.3 42.25 180 bottom
U39  -  [SOIC8]  62.3 63.65 180 bottom
U40  -  [SOIC8]  62.3 31.55 0 top
U41  -  [SOIC8]  62.3 52.95 0 top
U42  -  [SOIC8]  62.3 31.55 180 bottom
U43  -  [SOIC8]  62.3 52.95 180 bottom
U44  -  [SOIC8]  79.9 47.55 0 top
U45  -  [SOIC8]  79.9 68.95 0 top
U46  -  [SOIC8]  79.9 47.55 180 bottom
U47  -  [SOIC8]  79.9 68.95 180 bottom
U48  -  [SOIC8]  79.9 36.85 0 top
U49  -  [SOIC8]  79.9 58.25 0 top
U50  -  [SOIC8]  79.9 36.85 180 bottom
U51  -  [SOIC8]  79.9 58.25 180 bottom
U52  -  [SOIC8]  79.9 109.15 0 top
U53  -  [SOIC8]  79.9 109.15 180 bottom
U54  -  [SOIC8]  79.9 130.55 180 bottom
U55  -  [SOIC8]  79.9 98.45 0 top
U56  -  [SOIC8]  79.9 119.85 0 top
U57  -  [SOIC8]  79.9 98.45 180 bottom
U58  -  [SOIC8]  79.9 119.85 180 bottom
U59  -  [SOIC24-3_VER2]  95.4 130.55 0 top
U60  -  [SOIC24-3_VER2]  95.4 36.85 0 top
UXX  -  [unnamed#2]  133.5 61.75 0 top
UXX#2  -  [unnamed#2]  144.5 61.75 180 bottom

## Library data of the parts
C1 C2 C10 C12 C13 C24 C25 = CAPACITOR: alternate symbols: (SMD0603M); part number: CAPACITOR_0603-10N,+/-10%,AVX-KYOCERA
C3-C9 C11 C40-C45 C51 C52 C54 C55 C57 C58 C61-C64 C67 C70 C75-C77 C85-C90 C92 C93 C95 C96 C99 C101 C106-C109 C114 C115 C120 C121 C123 C124 C128 C129 C134-C136 C138 C142 C143 C148 C149 C151 C152 C156 C157 C162-C164 C166 C170 C171 C176-C181 C183 C186 C187 = CAPACITOR: alternate symbols: (SMD0603M); part number: CAPACITOR_0603-100N,+/-10%,AVX-KYOCERA
C14-C17 C20 C21 C26-C31 = CAPACITOR: alternate symbols: (SMD0402M); part number: CAPACITOR_0402-100N,+/-10%,MURATA
C18 C19 C32-C35 C53 C56 C65 C66 C68 C69 C94 C97 C98 C100 C110-C113 C122 C125-C127 C137 C139-C141 C150 C153-C155 C165 C167-C169 = CAPACITOR: alternate symbols: (SMD0603M); part number: CAPACITOR_0603-15P/50V,+/-5%,PHYCOMP
C22 C23 C36-C39 C59 C60 C71-C74 C82 C102-C105 C116-C119 C130-C133 C144-C147 C158-C161 C172-C175 = CAPACITOR: alternate symbols: (SMD0603M); part number: CAPACITOR_0603-100P,+/-5%,MULTICOMP
C46-C50 = CAPACITOR: part number: CAPACITOR_CASE-B-4U7,+/-10%,AVX-KYOCERA
C78 = CAPACITOR: part number: CAPACITOR_CASE-D-100U/25V,+/-10%,AVX
C79 C80 = CAPACITOR: Tolerance: ***; User Part Number: Kemet C1210C106K3RAC; alternate symbols: (SMD1210M); part number: CAPACITOR_1210-10U/25V,+/-10%,KEMET
C81 = CAPACITOR: alternate symbols: (SMD0603M); part number: CAPACITOR_0603-1N0,+/-5%,MURATA
C83 = CAPACITOR: alternate symbols: (SMD1206M); part number: CAPACITOR_1206-100U,+/-20%,KEMET
C84 = CAPACITOR: part number: CAPACITOR_CASE-E-470U/10V,+/-20%,AVX
C91 = CAPACITOR: part number: CAPACITOR_CASE-E-470U,+/-10%,AVX-KYOCERA
C182 C184 = CAPACITOR: alternate symbols: (SMD0805M); part number: CAPACITOR_0805-10U/6.3V,+/-10%,AVX
C185 = CAPACITOR: part number: CAPACITOR_CASE-A-10U,+/-10%,AVX-KYOCERA
DS1 = LED-SMD: Tolerance: ***; User Part Number: Dialight Corporation 5988110107F; part number: LED-SMD_0805-RED,DIALIGHT CORPORATION
DS2-DS4 = LED-SMD: Tolerance: ***; User Part Number: Agilent Technologies HSMG-C170; part number: LED-SMD_0805-GRN,AGILENT TECHNOLOGIES
DS5 = LED-SMD: part number: LED-SMD_C120-BLUE,AVAGO TECHNOLOGIES
DS6 = LED-SMD: part number: LED-SMD_C120-GREEN,AVAGO TECHNOLOGIES
LK5-LK8 = GROUND-BAR: part number: GROUND-BAR_0-4PITCH-HARWIN
LK9-LK12 = 1-HOLE: part number: 1-HOLE_0-8-BASE
PL1-PL7 = HEADER2X1: part number: HEADER2X1_STR-HARWIN
PL8 = UNIVERSAL-GUIDE-PIN: part number: UNIVERSAL-GUIDE-PIN_PTH-RA-45 DEGREES,TYCO ELECTRONICS
PL9 PL10 = PL-DIFF-30PAIRS: part number: PL-DIFF-30PAIRS_RT-ANG-ERNI
PL11 = HEADER1X8: part number: HEADER1X8_STR-HARWIN
R1 R2 R7 R9 R11 R13 R15 R17 R19 R69 R71 R73 R75 R77 R79 R81 R155 R157 R159 R270 R310 R312 R313 R315 R317 R318 = RESISTOR: alternate symbols: (SMD0603M); part number: RESISTOR_0603-0R0,1%,MULTICOMP
R3 R5 R30 R31 = RESISTOR: alternate symbols: (SMD0603M); part number: RESISTOR_0603-33R,0.1%,MEGGITT E.C
R4 R20 R21 R37 R67 R82 R83 R96 R97 R100 R101 R104 R111 R113 R114 R127 R128 R161 R162 R175 R176 R179 R180 R193 R194 R197 R198 R211 R212 R215 R216 R229 R230 R233 R234 R247 R248 R251 R252 R265 R266 R269 R273 = RESISTOR: alternate symbols: (SMD0603M); part number: RESISTOR_0603-100R,5%,ROHM
R6 R8 R10 R12 R14 R16 R18 R22 R23 R29 R35 R39 R68 R70 R72 R74 R76 R78 R80 R94 R95 R98 R99 R102 R103 R110 R112 R125 R126 R129-R131 R173 R174 R177 R178 R191 R192 R195 R196 R209 R210 R213 R214 R227 R228 R231 R232 R245 R246 R249 R250 R263 R264 R267 R268 R271 R272 = RESISTOR: alternate symbols: (SMD0603M); part number: RESISTOR_0603-1K0,5%,ROHM
R24 R26 R84 R86 R87 R89 R105 R107 R115 R117 R118 R120 R163 R165 R168 R170 R181 R183 R184 R186 R199 R201 R204 R206 R217 R219 R220 R222 R235 R237 R240 R242 R253 R255 R256 R258 = RESISTOR: alternate symbols: (SMD0603M); part number: RESISTOR_0603-4K7,5%,ROHM
R25 R85 R88 R106 R116 R119 R164 R169 R182 R185 R200 R205 R218 R221 R236 R241 R254 R257 = RESISTOR: alternate symbols: (SMD0603M); part number: RESISTOR_0603-2K2,5%,MULTICOMP
R27 R28 R90-R93 R108 R109 R121-R124 R166 R167 R171 R172 R187-R190 R202 R203 R207 R208 R223-R226 R238 R239 R243 R244 R259-R262 = RESISTOR: alternate symbols: (SMD0603M); part number: RESISTOR_0603-56K,1%,MULTICOMP
R32-R34 R36 R38 R40-R66 R132 = RESISTOR: alternate symbols: (SMD0402M); part number: RESISTOR_0402-330R,5%,PHILIPS
R133 = RESISTOR: alternate symbols: (SMD0603M); part number: RESISTOR_0603-3K3,5%,ROHM
R134 = RESISTOR: alternate symbols: (SMD0603M); part number: RESISTOR_0603-330R,1%,MULTICOMP
R135 = RESISTOR: alternate symbols: (SMD0603M); part number: RESISTOR_0603-47K,1%,MULTICOMP
R136 R137 = RESISTOR: alternate symbols: (SMD0603M); part number: RESISTOR_0603-30K,1%,MULTICOMP
R138-R143 R145-R150 R154 R156 R158 R160 R309 R311 R314 R316 = RESISTOR: alternate symbols: (SMD0603M); part number: RESISTOR_0603-10K,5%,ROHM
R144 = RESISTOR: alternate symbols: (SMD0603M); part number: RESISTOR_0603-22K1,0.1%,TYCO
R151 = RESISTOR: alternate symbols: (SMD0603M); part number: RESISTOR_0603-51R,1%,MULTICOMP
R152 R153 = RESISTOR: alternate symbols: (SMD0603M); part number: RESISTOR_0603-200R,1%,MULTICOMP
R274 R275 = RESISTOR: part number: RESISTOR_MGRF1W-10M,5%,MULTICOMP
SK2 = RJ45-VER2: part number: RJ45-VER2_RT-ANG-CAT6-WS-A,STEWART
SK4 = RJ45-2X8PORT: part number: RJ45-2X8PORT_RT-ANG-RJ45,TYCO ELECTRONICS
SW1 = 2WAY-SPST: part number: 2WAY-SPST_DIL-GRAYHILL
SW2 = AMC-MICROSWITCH: part number: AMC-MICROSWITCH_SMD-STR-SCHROFF
TP1-TP4 TP7 TP8 TP10-TP18 TP20-TP23 = VEROTP: part number: VEROTP_1.02MM-YELLOW,VERO
TP5 TP6 TP9 TP19 TP24 TP25 = VEROTP: part number: VEROTP_1.32MM-BLACK,VERO
U1 = NC7SZ04: part number: NC7SZ04_SOT-FAIRCHILD
U2 U7 U9 U13 U18-U29 U36-U58 = DS90LV001: part number: DS90LV001_SOIC-NATIONAL SEMI-CONDUCTOR
U3 = ICS527-01: part number: ICS527-01_SSOP-ICS
U4 U6 = DS90LV018A: part number: DS90LV018A_SOIC-NATIONAL SEMI-CONDUCTOR
U5 = 74LVC2G86: part number: 74LVC2G86_VSSOP-TEXAS INSTRUMENTS
U8 = 3D3225: part number: 3D3225_SOIC-5-TAP/10NS,DATA DELAY DEVICES
U10 = DS90LV027A: part number: DS90LV027A_SOIC-NATIONAL SEMI-CONDUCTOR
U11 U31 = 74LVC1G06: part number: 74LVC1G06_SOT23-5-TEXAS INSTRUMENTS
U12 U17 = 65LVDS116: part number: 65LVDS116_TSSOP-TEXAS INSTRUMENTS
U14 = ICS580-01: part number: ICS580-01_SOIC-IDT
U15 = OSC-SMD: part number: OSC-SMD_CFPS-73-9.0278MHZ,+/-50PPM,EUROQUARTZ
U16 = ICS581-02: part number: ICS581-02_TSSOP-INTEGRATED CIRCUIT SYSTEMS
U30 = 74LVC1G34: part number: 74LVC1G34_SOT-TEXAS INSTRUMENTS
U32 = PCF8574: part number: PCF8574_SOIC-NXP
U33 = LTM4600: part number: LTM4600_LGA-LINEAR TECHNOLOGY
U34 = AT24C32C: part number: AT24C32C_TSSOP-ATMEL
U35 = LM75A: part number: LM75A_SOIC-NATIONAL SEMICONDUCTOR
U59 U60 = STP16CP05: part number: STP16CP05_SOIC-ST ELECTRONICS

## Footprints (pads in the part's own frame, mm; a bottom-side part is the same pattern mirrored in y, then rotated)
1-HOLE_0-8P
  round 1.524 hole 0.813: 1(0,0)
1-HOLE_1-05P
  round 1.778 hole 1.067: 1(0,0)
AMC_MICROSWITCH_SMD_STR
  round 0.6 hole 0.6: (-0.85,0)
  round 0.8 hole 0.8 unplated: (0.85,0)
  rect 1x0.6 smd: A(-0.9,1.55) B(-0.9,-1.55) C(0.9,1.55) D(0.9,-1.55)
CASE_A
  rect 1.575x1.575 smd: 1(-1.321,0) 2(1.321,0)
CASE_B
  rect 1.524x2.54 smd: 1(-1.524,0) 2(1.524,0)
CASE_D
  rect 2.743x2.743 smd: 1(-3.277,0) 2(3.277,0)
CASE_E
  rect 2.743x2.743 smd: 1(-3.277,0) 2(3.277,0)
CFPS-73
  rect 1.803x2.007 smd: 1(-2.54,-2.1) 2(2.54,-2.1) 3(2.54,2.1) 4(-2.54,2.1)
HEADER1X8_STR
  rect 1.829x1.829 hole 1.118: 1(10.16,0)
  round 1.829 hole 1.118: 2(12.7,0) 3(15.24,0) 4(17.78,0) 5(20.32,0) 6(22.86,0) 7(25.4,0) 8(27.94,0)
HEADER2X1_STR
  rect 1.727x1.727 hole 1.016: 1(0,0)
  round 1.727 hole 1.016: 2(2.54,0)
JUMPER2X1_0-4
  round 1.93 hole 1.219: 1(0,0) 2(10.16,0)
LED_C120
  rect 0.4x0.4 smd: (0,0.35)
  rect 0.8x0.7 smd: 1(-1,0) 2(1,0)
LGA104
  round 1 smd: (-9.985,-9.985) (10.015,10.015) (10.015,-9.985)
  rect 0.64x0.64 smd: A3(-5.716,6.989) A5(-4.446,6.989) A7(-3.176,6.989) A9(-1.906,6.989) A11(-0.636,6.989) A13(0.634,6.989) A15(1.904,6.989) A17(3.174,6.989) A19(4.444,6.989) A21(5.714,6.989) B1(-6.942,6.548) B23(6.986,6.548) C10(-1.27,5.765) C12(0,5.765) C14(1.27,5.765) D1(-6.942,5.278) D23(6.986,5.278) E10(-1.27,4.495) E12(0,4.495) E14(1.27,4.495) F1(-6.942,4.008) F23(6.986,4.008) G1(-6.942,2.738) G23(6.986,2.738) H7(-3.176,2.36) H9(-1.906,2.36) H11(-0.636,2.36) H13(0.634,2.36) H15(1.904,2.36) H17(3.174,2.36) J1(-6.942,1.468) J23(6.986,1.468) K7(-3.176,1.09) K9(-1.906,1.09) K11(-0.636,1.09) K13(0.634,1.09) K15(1.904,1.09) K17(3.174,1.09) L2(-6.35,0) L4(-5.08,0) L6(-3.81,0) L8(-2.54,0) L10(-1.27,0) L12(0,0) L14(1.27,0) L16(2.54,0) L18(3.81,0) L20(5.08,0) L22(6.35,0) M2(-6.35,-1.27) M4(-5.08,-1.27) M6(-3.81,-1.27) M8(-2.54,-1.27) M10(-1.27,-1.27) M12(0,-1.27) M14(1.27,-1.27) M16(2.54,-1.27) M18(3.81,-1.27) M20(5.08,-1.27) M22(6.35,-1.27) N2(-6.35,-2.54) N4(-5.08,-2.54) N6(-3.81,-2.54) N8(-2.54,-2.54) N10(-1.27,-2.54) N12(0,-2.54) N14(1.27,-2.54) N16(2.54,-2.54) N18(3.81,-2.54) N20(5.08,-2.54) N22(6.35,-2.54) P2(-6.35,-4.445) P4(-5.08,-4.445) P6(-3.81,-4.445) P8(-2.54,-4.445) P10(-1.27,-4.445) P12(0,-4.445) P14(1.27,-4.445) P16(2.54,-4.445) P18(3.81,-4.445) P20(5.08,-4.445) P22(6.35,-4.445) R2(-6.35,-5.715) R4(-5.08,-5.715) R6(-3.81,-5.715) R8(-2.54,-5.715) R10(-1.27,-5.715) R12(0,-5.715) R14(1.27,-5.715) R16(2.54,-5.715) R18(3.81,-5.715) R20(5.08,-5.715) R22(6.35,-5.715) T2(-6.35,-6.985) T4(-5.08,-6.985) T6(-3.81,-6.985) T8(-2.54,-6.985) T10(-1.27,-6.985) T12(0,-6.985) T14(1.27,-6.985) T16(2.54,-6.985) T18(3.81,-6.985) T20(5.08,-6.985) T22(6.35,-6.985)
MGRF1W
  rect 1.626x1.626 hole 1.016: 1(-9.5,0)
  round 1.626 hole 1.016: 2(9.5,0)
PL_DIFF_30PAIRS_RT-ANG
  rect 1.016x1.016 hole 0.61: A1(0,0)
  round 1.016 hole 0.61: A2(2.5,0) A3(5,0) A4(7.5,0) A5(10,0) A6(12.5,0) A7(15,0) A8(17.5,0) A9(20,0) A10(22.5,0) AB1(0,3) AB2(2.5,3) AB3(5,3) AB4(7.5,3) AB5(10,3) AB6(12.5,3) AB7(15,3) AB8(17.5,3) AB9(20,3) AB10(22.5,3) B1(0,1.5) B2(2.5,1.5) B3(5,1.5) B4(7.5,1.5) B5(10,1.5) B6(12.5,1.5) B7(15,1.5) B8(17.5,1.5) B9(20,1.5) B10(22.5,1.5) C1(0,4.5) C2(2.5,4.5) C3(5,4.5) C4(7.5,4.5) C5(10,4.5) C6(12.5,4.5) C7(15,4.5) C8(17.5,4.5) C9(20,4.5) C10(22.5,4.5) CD1(0,7.5) CD2(2.5,7.5) CD3(5,7.5) CD4(7.5,7.5) CD5(10,7.5) CD6(12.5,7.5) CD7(15,7.5) CD8(17.5,7.5) CD9(20,7.5) CD10(22.5,7.5) D1(0,6) D2(2.5,6) D3(5,6) D4(7.5,6) D5(10,6) D6(12.5,6) D7(15,6) D8(17.5,6) D9(20,6) D10(22.5,6) E1(0,9) E2(2.5,9) E3(5,9) E4(7.5,9) E5(10,9) E6(12.5,9) E7(15,9) E8(17.5,9) E9(20,9) E10(22.5,9) EF1(0,12) EF2(2.5,12) EF3(5,12) EF4(7.5,12) EF5(10,12) EF6(12.5,12) EF7(15,12) EF8(17.5,12) EF9(20,12) EF10(22.5,12) F1(0,10.5) F2(2.5,10.5) F3(5,10.5) F4(7.5,10.5) F5(10,10.5) F6(12.5,10.5) F7(15,10.5) F8(17.5,10.5) F9(20,10.5) F10(22.5,10.5)
RJ45_2X8PORT_RT
  rect 1.321x1.321 hole 0.914: 1LA(0,0) 1LB(14.605,0) 1LC(29.21,0) 1LD(43.815,0) 1LE(58.42,0) 1LF(73.025,0) 1LG(87.63,0) 1LH(102.235,0) 1UA(7.112,9.144) 1UB(21.717,9.144) 1UC(36.322,9.144) 1UD(50.927,9.144) 1UE(65.532,9.144) 1UF(80.137,9.144) 1UG(94.742,9.144) 1UH(109.347,9.144)
  round 1.321 hole 0.914: 2LA(1.016,2.54) 2LB(15.621,2.54) 2LC(30.226,2.54) 2LD(44.831,2.54) 2LE(59.436,2.54) 2LF(74.041,2.54) 2LG(88.646,2.54) 2LH(103.251,2.54) 2UA(6.096,6.604) 2UB(20.701,6.604) 2UC(35.306,6.604) 2UD(49.911,6.604) 2UE(64.516,6.604) 2UF(79.121,6.604) 2UG(93.726,6.604) 2UH(108.331,6.604) 3LA(2.032,0) 3LB(16.637,0) 3LC(31.242,0) 3LD(45.847,0) 3LE(60.452,0) 3LF(75.057,0) 3LG(89.662,0) 3LH(104.267,0) 3UA(5.08,9.144) 3UB(19.685,9.144) 3UC(34.29,9.144) 3UD(48.895,9.144) 3UE(63.5,9.144) 3UF(78.105,9.144) 3UG(92.71,9.144) 3UH(107.315,9.144) 4LA(3.048,2.54) 4LB(17.653,2.54) 4LC(32.258,2.54) 4LD(46.863,2.54) 4LE(61.468,2.54) 4LF(76.073,2.54) 4LG(90.678,2.54) 4LH(105.283,2.54) 4UA(4.064,6.604) 4UB(18.669,6.604) 4UC(33.274,6.604) 4UD(47.879,6.604) 4UE(62.484,6.604) 4UF(77.089,6.604) 4UG(91.694,6.604) 4UH(106.299,6.604) 5LA(4.064,0) 5LB(18.669,0) 5LC(33.274,0) 5LD(47.879,0) 5LE(62.484,0) 5LF(77.089,0) 5LG(91.694,0) 5LH(106.299,0) 5UA(3.048,9.144) 5UB(17.653,9.144) 5UC(32.258,9.144) 5UD(46.863,9.144) 5UE(61.468,9.144) 5UF(76.073,9.144) 5UG(90.678,9.144) 5UH(105.283,9.144) 6LA(5.08,2.54) 6LB(19.685,2.54) 6LC(34.29,2.54) 6LD(48.895,2.54) 6LE(63.5,2.54) 6LF(78.105,2.54) 6LG(92.71,2.54) 6LH(107.315,2.54) 6UA(2.032,6.604) 6UB(16.637,6.604) 6UC(31.242,6.604) 6UD(45.847,6.604) 6UE(60.452,6.604) 6UF(75.057,6.604) 6UG(89.662,6.604) 6UH(104.267,6.604) 7LA(6.096,0) 7LB(20.701,0) 7LC(35.306,0) 7LD(49.911,0) 7LE(64.516,0) 7LF(79.121,0) 7LG(93.726,0) 7LH(108.331,0) 7UA(1.016,9.144) 7UB(15.621,9.144) 7UC(30.226,9.144) 7UD(44.831,9.144) 7UE(59.436,9.144) 7UF(74.041,9.144) 7UG(88.646,9.144) 7UH(103.251,9.144) 8LA(7.112,2.54) 8LB(21.717,2.54) 8LC(36.322,2.54) 8LD(50.927,2.54) 8LE(65.532,2.54) 8LF(80.137,2.54) 8LG(94.742,2.54) 8LH(109.347,2.54) 8UA(0,6.604) 8UB(14.605,6.604) 8UC(29.21,6.604) 8UD(43.815,6.604) 8UE(58.42,6.604) 8UF(73.025,6.604) 8UG(87.63,6.604) 8UH(102.235,6.604) GND1(-4.318,3.81) GND2(-4.318,0) GND3(113.665,3.81) GND4(113.665,0) GND5(10.871,10.77) GND6(25.476,10.77) GND7(40.081,10.77) GND8(54.686,10.77) GND9(69.291,10.77) GND10(83.896,10.77) GND11(98.501,10.77) LLLA_A(-2.73,-5.08) LLLA_K(-0.19,-5.08) LLLB_A(11.874,-5.08) LLLB_K(14.414,-5.08) LLLC_A(26.48,-5.08) LLLC_K(29.02,-5.08) LLLD_A(41.084,-5.08) LLLD_K(43.624,-5.08) LLLE_A(55.69,-5.08) LLLE_K(58.23,-5.08) LLLF_A(70.294,-5.08) LLLF_K(72.834,-5.08) LLLG_A(84.9,-5.08) LLLG_K(87.44,-5.08) LLLH_A(99.504,-5.08) LLLH_K(102.044,-5.08) LRLA_A(7.302,-5.08) LRLA_K(9.842,-5.08) LRLB_A(21.908,-5.08) LRLB_K(24.448,-5.08) LRLC_A(36.512,-5.08) LRLC_K(39.052,-5.08) LRLD_A(51.118,-5.08) LRLD_K(53.658,-5.08) LRLE_A(65.722,-5.08) LRLE_K(68.262,-5.08) LRLF_A(80.328,-5.08) LRLF_K(82.868,-5.08) LRLG_A(94.932,-5.08) LRLG_K(97.472,-5.08) LRLH_A(109.538,-5.08) LRLH_K(112.078,-5.08) ULLA_A(-2.73,-2.54) ULLA_K(-0.19,-2.54) ULLB_A(11.874,-2.54) ULLB_K(14.414,-2.54) ULLC_A(26.48,-2.54) ULLC_K(29.02,-2.54) ULLD_A(41.084,-2.54) ULLD_K(43.624,-2.54) ULLE_A(55.69,-2.54) ULLE_K(58.23,-2.54) ULLF_A(70.294,-2.54) ULLF_K(72.834,-2.54) ULLG_A(84.9,-2.54) ULLG_K(87.44,-2.54) ULLH_A(99.504,-2.54) ULLH_K(102.044,-2.54) URLA_A(7.302,-2.54) URLA_K(9.842,-2.54) URLB_A(21.908,-2.54) URLB_K(24.448,-2.54) URLC_A(36.512,-2.54) URLC_K(39.052,-2.54) URLD_A(51.118,-2.54) URLD_K(53.658,-2.54) URLE_A(65.722,-2.54) URLE_K(68.262,-2.54) URLF_A(80.328,-2.54) URLF_K(82.868,-2.54) URLG_A(94.932,-2.54) URLG_K(97.472,-2.54) URLH_A(109.538,-2.54) URLH_K(112.078,-2.54)
RJ45_CAT6_WS_VER1
  round 3.2 hole 3.302 unplated: (-5.715,-6.35) (5.715,-6.35)
  rect 1.321x1.321 hole 0.914: 1(2.541,0.68)
  round 1.321 hole 0.914: 2(3.557,-1.35) 3(1.525,-1.35) 4(-0.507,-1.35) 5(0.509,0.68) 6(-1.523,0.68) 7(-3.555,0.68) 8(-2.539,-1.35)
  round 2.337 hole 1.6: 9(-7.8,-9.86) 10(7.8,-9.86)
SMD0402
  rect 0.35x0.6 smd: 1(-0.43,0) 2(0.43,0)
SMD0603
  rect 0.93x1 smd: 1(-0.865,0) 2(0.865,0)
SMD0603M
  rect 0.93x1 smd: 1(-0.865,0) 2(0.865,0)
SMD0805_LED
  rect 1.016x1.727 smd: 1(-1.016,0) 2(1.016,0)
SMD0805M
  rect 1.01x1.45 smd: 1(-1.005,0) 2(1.005,0)
SMD1206
  rect 1.31x1.7 smd: 1(-1.455,0) 2(1.455,0)
SMD1210M
  rect 1.27x2.65 smd: 1(-1.55,0) 2(1.55,0)
SOIC8
  rect 1.27x0.635 smd: 1(-2.667,1.905) 2(-2.667,0.635) 3(-2.667,-0.635) 4(-2.667,-1.905) 5(2.667,-1.905) 6(2.667,-0.635) 7(2.667,0.635) 8(2.667,1.905)
SOIC16
  rect 1.27x0.635 smd: 1(-2.667,4.445) 2(-2.667,3.175) 3(-2.667,1.905) 4(-2.667,0.635) 5(-2.667,-0.635) 6(-2.667,-1.905) 7(-2.667,-3.175) 8(-2.667,-4.445) 9(2.667,-4.445) 10(2.667,-3.175) 11(2.667,-1.905) 12(2.667,-0.635) 13(2.667,0.635) 14(2.667,1.905) 15(2.667,3.175) 16(2.667,4.445)
SOIC16-3
  rect 1.27x0.635 smd: 1(-4.826,4.445) 2(-4.826,3.175) 3(-4.826,1.905) 4(-4.826,0.635) 5(-4.826,-0.635) 6(-4.826,-1.905) 7(-4.826,-3.175) 8(-4.826,-4.445) 9(4.826,-4.445) 10(4.826,-3.175) 11(4.826,-1.905) 12(4.826,-0.635) 13(4.826,0.635) 14(4.826,1.905) 15(4.826,3.175) 16(4.826,4.445)
SOIC24-3_VER2
  rect 2.1x0.6 smd: 1(-4.65,6.985) 2(-4.65,5.715) 3(-4.65,4.445) 4(-4.65,3.175) 5(-4.65,1.905) 6(-4.65,0.635) 7(-4.65,-0.635) 8(-4.65,-1.905) 9(-4.65,-3.175) 10(-4.65,-4.445) 11(-4.65,-5.715) 12(-4.65,-6.985) 13(4.65,-6.985) 14(4.65,-5.715) 15(4.65,-4.445) 16(4.65,-3.175) 17(4.65,-1.905) 18(4.65,-0.635) 19(4.65,0.635) 20(4.65,1.905) 21(4.65,3.175) 22(4.65,4.445) 23(4.65,5.715) 24(4.65,6.985)
SOT23-5
  rect 0.635x0.508 smd: 1(-1.245,0.94) 2(-1.245,0) 3(-1.245,-0.94) 4(1.245,-0.94) 5(1.245,0.94)
SOT23-5_VER2
  rect 1.016x0.635 smd: 1(-1.295,0.94) 2(-1.295,0) 3(-1.295,-0.94) 4(1.295,-0.94) 5(1.295,0.94)
SOT23-5_VER4
  rect 0.635x0.356 smd: 1(-0.864,0.66) 2(-0.864,0) 3(-0.864,-0.66) 4(0.864,-0.66) 5(0.864,0.66)
SSOP28_IDT_VER2
  rect 1.55x0.4 smd: 1(-2.7,4.128) 2(-2.7,3.492) 3(-2.7,2.858) 4(-2.7,2.222) 5(-2.7,1.588) 6(-2.7,0.952) 7(-2.7,0.318) 8(-2.7,-0.318) 9(-2.7,-0.952) 10(-2.7,-1.588) 11(-2.7,-2.222) 12(-2.7,-2.858) 13(-2.7,-3.492) 14(-2.7,-4.128) 15(2.7,-4.128) 16(2.7,-3.492) 17(2.7,-2.858) 18(2.7,-2.222) 19(2.7,-1.588) 20(2.7,-0.952) 21(2.7,-0.318) 22(2.7,0.318) 23(2.7,0.952) 24(2.7,1.588) 25(2.7,2.222) 26(2.7,2.858) 27(2.7,3.492) 28(2.7,4.128)
SW4-3
  rect 1.524x1.524 hole 0.813: 1(-3.81,3.81)
  round 1.524 hole 0.813: 2(-3.81,1.27) 3(3.81,1.27) 4(3.81,3.81)
TSSOP8_VER6
  rect 1.5x0.45 smd: 1(-2.9,0.975) 2(-2.9,0.325) 3(-2.9,-0.325) 4(-2.9,-0.975) 5(2.9,-0.975) 6(2.9,-0.325) 7(2.9,0.325) 8(2.9,0.975)
TSSOP16
  rect 1.016x0.254 smd: 1(-2.95,2.275) 2(-2.95,1.625) 3(-2.95,0.975) 4(-2.95,0.325) 5(-2.95,-0.325) 6(-2.95,-0.975) 7(-2.95,-1.625) 8(-2.95,-2.275) 9(2.95,-2.275) 10(2.95,-1.625) 11(2.95,-0.975) 12(2.95,-0.325) 13(2.95,0.325) 14(2.95,0.975) 15(2.95,1.625) 16(2.95,2.275)
TSSOP64_VER2
  rect 1.6x0.3 smd: 1(-3.7,7.75) 2(-3.7,7.25) 3(-3.7,6.75) 4(-3.7,6.25) 5(-3.7,5.75) 6(-3.7,5.25) 7(-3.7,4.75) 8(-3.7,4.25) 9(-3.7,3.75) 10(-3.7,3.25) 11(-3.7,2.75) 12(-3.7,2.25) 13(-3.7,1.75) 14(-3.7,1.25) 15(-3.7,0.75) 16(-3.7,0.25) 17(-3.7,-0.25) 18(-3.7,-0.75) 19(-3.7,-1.25) 20(-3.7,-1.75) 21(-3.7,-2.25) 22(-3.7,-2.75) 23(-3.7,-3.25) 24(-3.7,-3.75) 25(-3.7,-4.25) 26(-3.7,-4.75) 27(-3.7,-5.25) 28(-3.7,-5.75) 29(-3.7,-6.25) 30(-3.7,-6.75) 31(-3.7,-7.25) 32(-3.7,-7.75) 33(3.7,-7.75) 34(3.7,-7.25) 35(3.7,-6.75) 36(3.7,-6.25) 37(3.7,-5.75) 38(3.7,-5.25) 39(3.7,-4.75) 40(3.7,-4.25) 41(3.7,-3.75) 42(3.7,-3.25) 43(3.7,-2.75) 44(3.7,-2.25) 45(3.7,-1.75) 46(3.7,-1.25) 47(3.7,-0.75) 48(3.7,-0.25) 49(3.7,0.25) 50(3.7,0.75) 51(3.7,1.25) 52(3.7,1.75) 53(3.7,2.25) 54(3.7,2.75) 55(3.7,3.25) 56(3.7,3.75) 57(3.7,4.25) 58(3.7,4.75) 59(3.7,5.25) 60(3.7,5.75) 61(3.7,6.25) 62(3.7,6.75) 63(3.7,7.25) 64(3.7,7.75)
UNIVERSAL_GUIDE_PIN
  round 5 hole 3.2: A(0,0) B(6.48,0) C(12.96,0)
unnamed#2
  rect 1.27x0.635 smd: 1(-2.667,4.445) 2(-2.667,3.175) 3(-2.667,1.905) 4(-2.667,0.635) 5(-2.667,-0.635) 6(-2.667,-1.905) 7(-2.667,-3.175) 8(-2.667,-4.445) 9(2.667,-4.445) 10(2.667,-3.175) 11(2.667,-1.905) 12(2.667,-0.635) 13(2.667,0.635) 14(2.667,1.905) 15(2.667,3.175) 16(2.667,4.445)
unnamed#3
  round 3.988 hole 2.692: (0,0)
VERO_TP_1_32MM
  round 2.032 hole 1.321: 1(0,0)
VSSOP8
  rect 1.016x0.254 smd: 1(-1.44,0.75) 2(-1.44,0.25) 3(-1.44,-0.25) 4(-1.44,-0.75) 5(1.44,-0.75) 6(1.44,-0.25) 7(1.44,0.25) 8(1.44,0.75)

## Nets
3V3: C1.2(B<0>) C2.2(B<0>) C3.2(B<0>) C4.1(A<0>) C5.2(B<0>) C6.2(B<0>) C7.2(B<0>) C8.2(B<0>) C9.2(B<0>) C10.2(B<0>) C11.2(B<0>) C12.2(B<0>) C13.2(B<0>) C14.2(B<0>) C15.2(B<0>) C16.2(B<0>) C17.2(B<0>) C20.2(B<0>) C21.2(B<0>) C24.2(B<0>) C25.2(B<0>) C26.2(B<0>) C27.2(B<0>) C28.2(B<0>) C29.2(B<0>) C30.2(B<0>) C31.2(B<0>) C40.2(B<0>) C41.2(B<0>) C42.2(B<0>) C43.2(B<0>) C44.2(B<0>) C45.2(B<0>) C46.2(B<0>) C47.2(B<0>) C48.2(B<0>) C49.2(B<0>) C50.2(B<0>) C51.2(B<0>) C52.2(B<0>) C54.2(B<0>) C55.2(B<0>) C57.2(B<0>) C58.2(B<0>) C61.2(B<0>) C62.2(B<0>) C63.2(B<0>) C64.2(B<0>) C67.2(B<0>) C70.2(B<0>) C75.2(B<0>) C76.2(B<0>) C82.2(B<0>) C83.2(B<0>) C84.2(B<0>) C92.2(B<0>) C93.2(B<0>) C95.2(B<0>) C96.2(B<0>) C99.2(B<0>) C101.2(B<0>) C106.2(B<0>) C107.2(B<0>) C108.2(B<0>) C109.2(B<0>) C114.2(B<0>) C115.2(B<0>) C120.2(B<0>) C121.2(B<0>) C123.2(B<0>) C124.2(B<0>) C128.2(B<0>) C129.2(B<0>) C134.2(B<0>) C135.2(B<0>) C136.2(B<0>) C138.2(B<0>) C142.2(B<0>) C143.2(B<0>) C148.2(B<0>) C149.2(B<0>) C151.2(B<0>) C152.2(B<0>) C156.2(B<0>) C157.2(B<0>) C162.2(B<0>) C163.2(B<0>) C164.2(B<0>) C166.2(B<0>) C170.2(B<0>) C171.2(B<0>) C176.2(B<0>) C177.2(B<0>) C178.2(B<0>) C179.2(B<0>) C181.2(B<0>) C182.2(B<0>) C183.2(B<0>) C184.2(B<0>) C185.2(B<0>) C186.2(B<0>) C187.2(B<0>) LK11.1(A<0>) LK12.1(A<0>) R6.2(B<0>) R8.2(B<0>) R10.2(B<0>) R12.2(B<0>) R14.2(B<0>) R16.2(B<0>) R18.2(B<0>) R22.2(B<0>) R23.2(B<0>) R27.2(B<0>) R29.2(B<0>) R32.1(A<0>) R33.1(A<0>) R34.1(A<0>) R35.2(B<0>) R36.1(A<0>) R38.1(A<0>) R39.2(B<0>) R40.1(A<0>) R41.1(A<0>) R42.1(A<0>) R43.1(A<0>) R44.1(A<0>) R45.1(A<0>) R46.1(A<0>) R47.1(A<0>) R48.1(A<0>) R49.1(A<0>) R50.1(A<0>) R51.2(B<0>) R52.2(B<0>) R53.2(B<0>) R54.2(B<0>) R55.2(B<0>) R56.2(B<0>) R57.2(B<0>) R58.2(B<0>) R59.2(B<0>) R60.2(B<0>) R61.2(B<0>) R62.2(B<0>) R63.2(B<0>) R64.2(B<0>) R65.2(B<0>) R66.2(B<0>) R68.2(B<0>) R70.2(B<0>) R72.2(B<0>) R74.2(B<0>) R76.2(B<0>) R78.2(B<0>) R80.2(B<0>) R92.2(B<0>) R93.2(B<0>) R94.2(B<0>) R95.2(B<0>) R98.2(B<0>) R99.2(B<0>) R102.2(B<0>) R103.2(B<0>) R108.2(B<0>) R110.2(B<0>) R112.2(B<0>) R121.2(B<0>) R123.2(B<0>) R125.2(B<0>) R126.2(B<0>) R129.2(B<0>) R130.2(B<0>) R133.2(B<0>) R166.2(B<0>) R171.2(B<0>) R173.2(B<0>) R174.2(B<0>) R177.2(B<0>) R178.2(B<0>) R187.2(B<0>) R189.2(B<0>) R191.2(B<0>) R192.2(B<0>) R195.2(B<0>) R196.2(B<0>) R202.2(B<0>) R207.2(B<0>) R209.2(B<0>) R210.2(B<0>) R213.2(B<0>) R214.2(B<0>) R223.2(B<0>) R225.2(B<0>) R227.2(B<0>) R228.2(B<0>) R231.2(B<0>) R232.2(B<0>) R238.2(B<0>) R243.2(B<0>) R245.2(B<0>) R246.2(B<0>) R249.2(B<0>) R250.2(B<0>) R259.2(B<0>) R261.2(B<0>) R263.2(B<0>) R264.2(B<0>) R267.2(B<0>) R268.2(B<0>) TP6.1(TEST<0>) U1.5 U2.5(VCC) U3.6(VDD1) U3.23(VDD2) U4.8(VCC) U5.8(VCC) U6.8(VCC) U7.5(VCC) U8.8(VDD) U9.5(VCC) U10.1(VCC) U11.5(VCC) U12.2(VCC1) U12.3(VCC2) U12.16(VCC3) U12.17(VCC4) U12.30(VCC5) U12.31(VCC6) U13.5(VCC) U14.3(VDDI) U14.15(VDDC) U15.4(VDD) U16.3(VDD1) U16.15(VDD2) U17.2(VCC1) U17.3(VCC2) U17.16(VCC3) U17.17(VCC4) U17.30(VCC5) U17.31(VCC6) U18.5(VCC) U19.5(VCC) U20.5(VCC) U21.5(VCC) U22.5(VCC) U23.5(VCC) U24.5(VCC) U25.5(VCC) U26.5(VCC) U27.5(VCC) U28.5(VCC) U29.5(VCC) U30.5(VCC) U33.P2(VOUT1) U33.P4(VOUT2) U33.P6(VOUT3) U33.P8(VOUT4) U33.P10(VOUT5) U33.P12(VOUT6) U33.P14(VOUT7) U33.P16(VOUT8) U33.P18(VOUT9) U33.P20(VOUT10) U33.P22(VOUT11) U33.R2(VOUT12) U33.R4(VOUT13) U33.R6(VOUT14) U33.R8(VOUT15) U33.R10(VOUT16) U33.R12(VOUT17) U33.R14(VOUT18) U33.R16(VOUT19) U33.R18(VOUT20) U33.R20(VOUT21) U33.R22(VOUT22) U33.T2(VOUT23) U33.T4(VOUT24) U33.T6(VOUT25) U33.T8(VOUT26) U33.T10(VOUT27) U33.T12(VOUT28) U33.T14(VOUT29) U33.T16(VOUT30) U33.T18(VOUT31) U33.T20(VOUT32) U33.T22(VOUT33) U36.5(VCC) U37.5(VCC) U38.5(VCC) U39.5(VCC) U40.5(VCC) U41.5(VCC) U42.5(VCC) U43.5(VCC) U44.5(VCC) U45.5(VCC) U46.5(VCC) U47.5(VCC) U48.5(VCC) U49.5(VCC) U50.5(VCC) U51.5(VCC) U52.5(VCC) U53.5(VCC) U54.5(VCC) U55.5(VCC) U56.5(VCC) U57.5(VCC) U58.5(VCC) U59.24(VDD) U60.24(VDD)
3V3_MP: C77.2(B<0>) C85.2(B<0>) C86.2(B<0>) C87.2(B<0>) C88.2(B<0>) C89.2(B<0>) C90.2(B<0>) C91.2(B<0>) C180.2(B<0>) PL9.C2(PAIR12_A) R132.1(A<0>) R138.2(B<0>) R139.2(B<0>) R140.2(B<0>) R141.2(B<0>) R142.2(B<0>) R143.2(B<0>) R145.2(B<0>) R146.2(B<0>) R147.2(B<0>) R148.2(B<0>) R149.2(B<0>) R150.2(B<0>) R151.1(A<0>) R152.1(A<0>) R153.1(A<0>) R154.2(B<0>) R156.2(B<0>) R158.2(B<0>) R160.2(B<0>) R309.2(B<0>) R311.2(B<0>) R314.2(B<0>) R316.2(B<0>) TP9.1(TEST<0>) U31.5(VCC) U32.16(VDD) U34.8(VCC) U35.8(+VS)
3V3_OK: R133.1(A<0>) U30.2(A) U33.J23(PGOOD)
12V: C78.2(B<0>) C79.2(B<0>) C80.2(B<0>) PL9.A1(PAIR1_A) PL9.A2(PAIR2_A) PL9.B1(PAIR1_B) PL9.B2(PAIR2_B) R131.1(A<0>) R135.2(B<0>) TP25.1(TEST<0>) U33.A3(VIN1) U33.A5(VIN2) U33.A7(VIN3) U33.A9(VIN4) U33.A11(VIN5) U33.A13(VIN6) U33.B1(VIN7) U33.C10(VIN8) U33.C12(VIN9) U33.C14(VIN10) U33.D1(VIN11) U33.E10(VIN12) U33.E12(VIN13) U33.E14(VIN14) U33.F1(VIN15)
